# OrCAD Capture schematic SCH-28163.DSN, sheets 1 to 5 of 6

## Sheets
1 1. Title Page: title: FRDM-K64F; rev: D1; company: Freescale Semiconductor; note: SCH-28163 | PDF: SPF-28163; note: 6501 William Cannon Drive West; note: Austin, TX 78735-8598
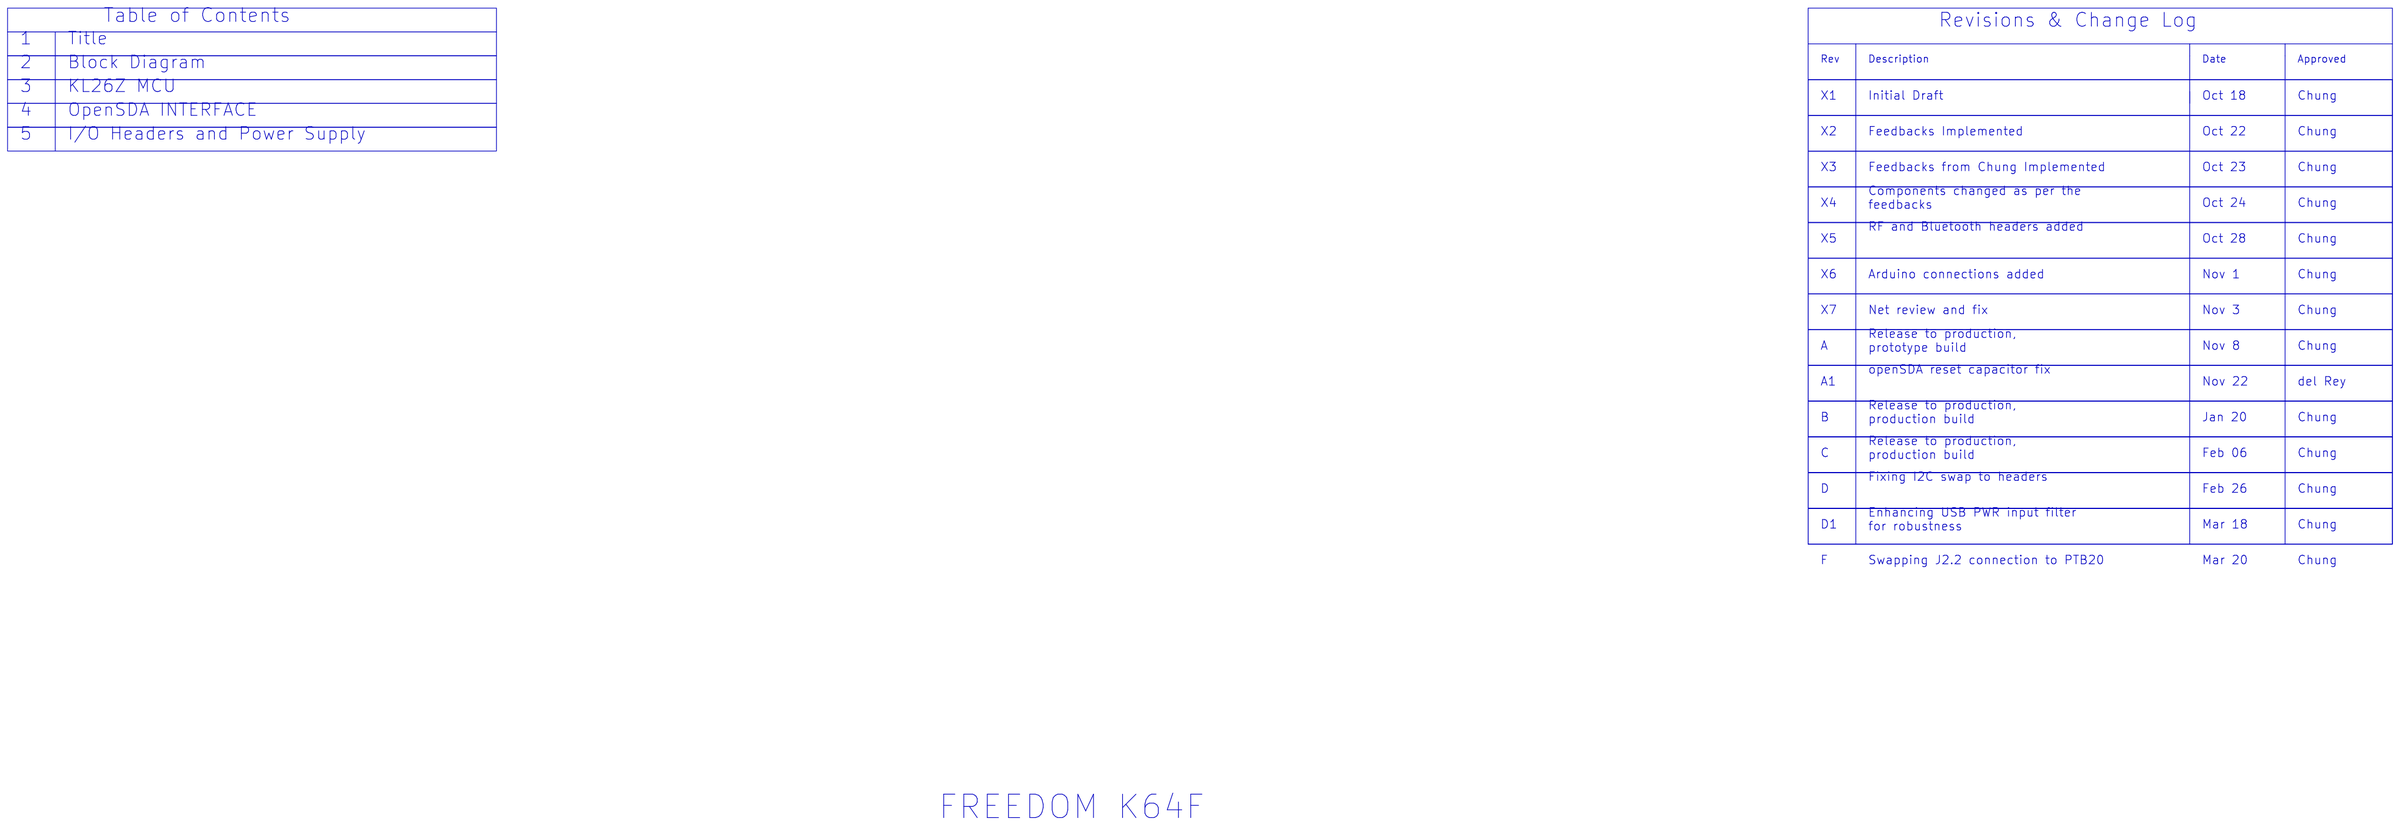
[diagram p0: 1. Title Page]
2 2. KL64F MCU: size C
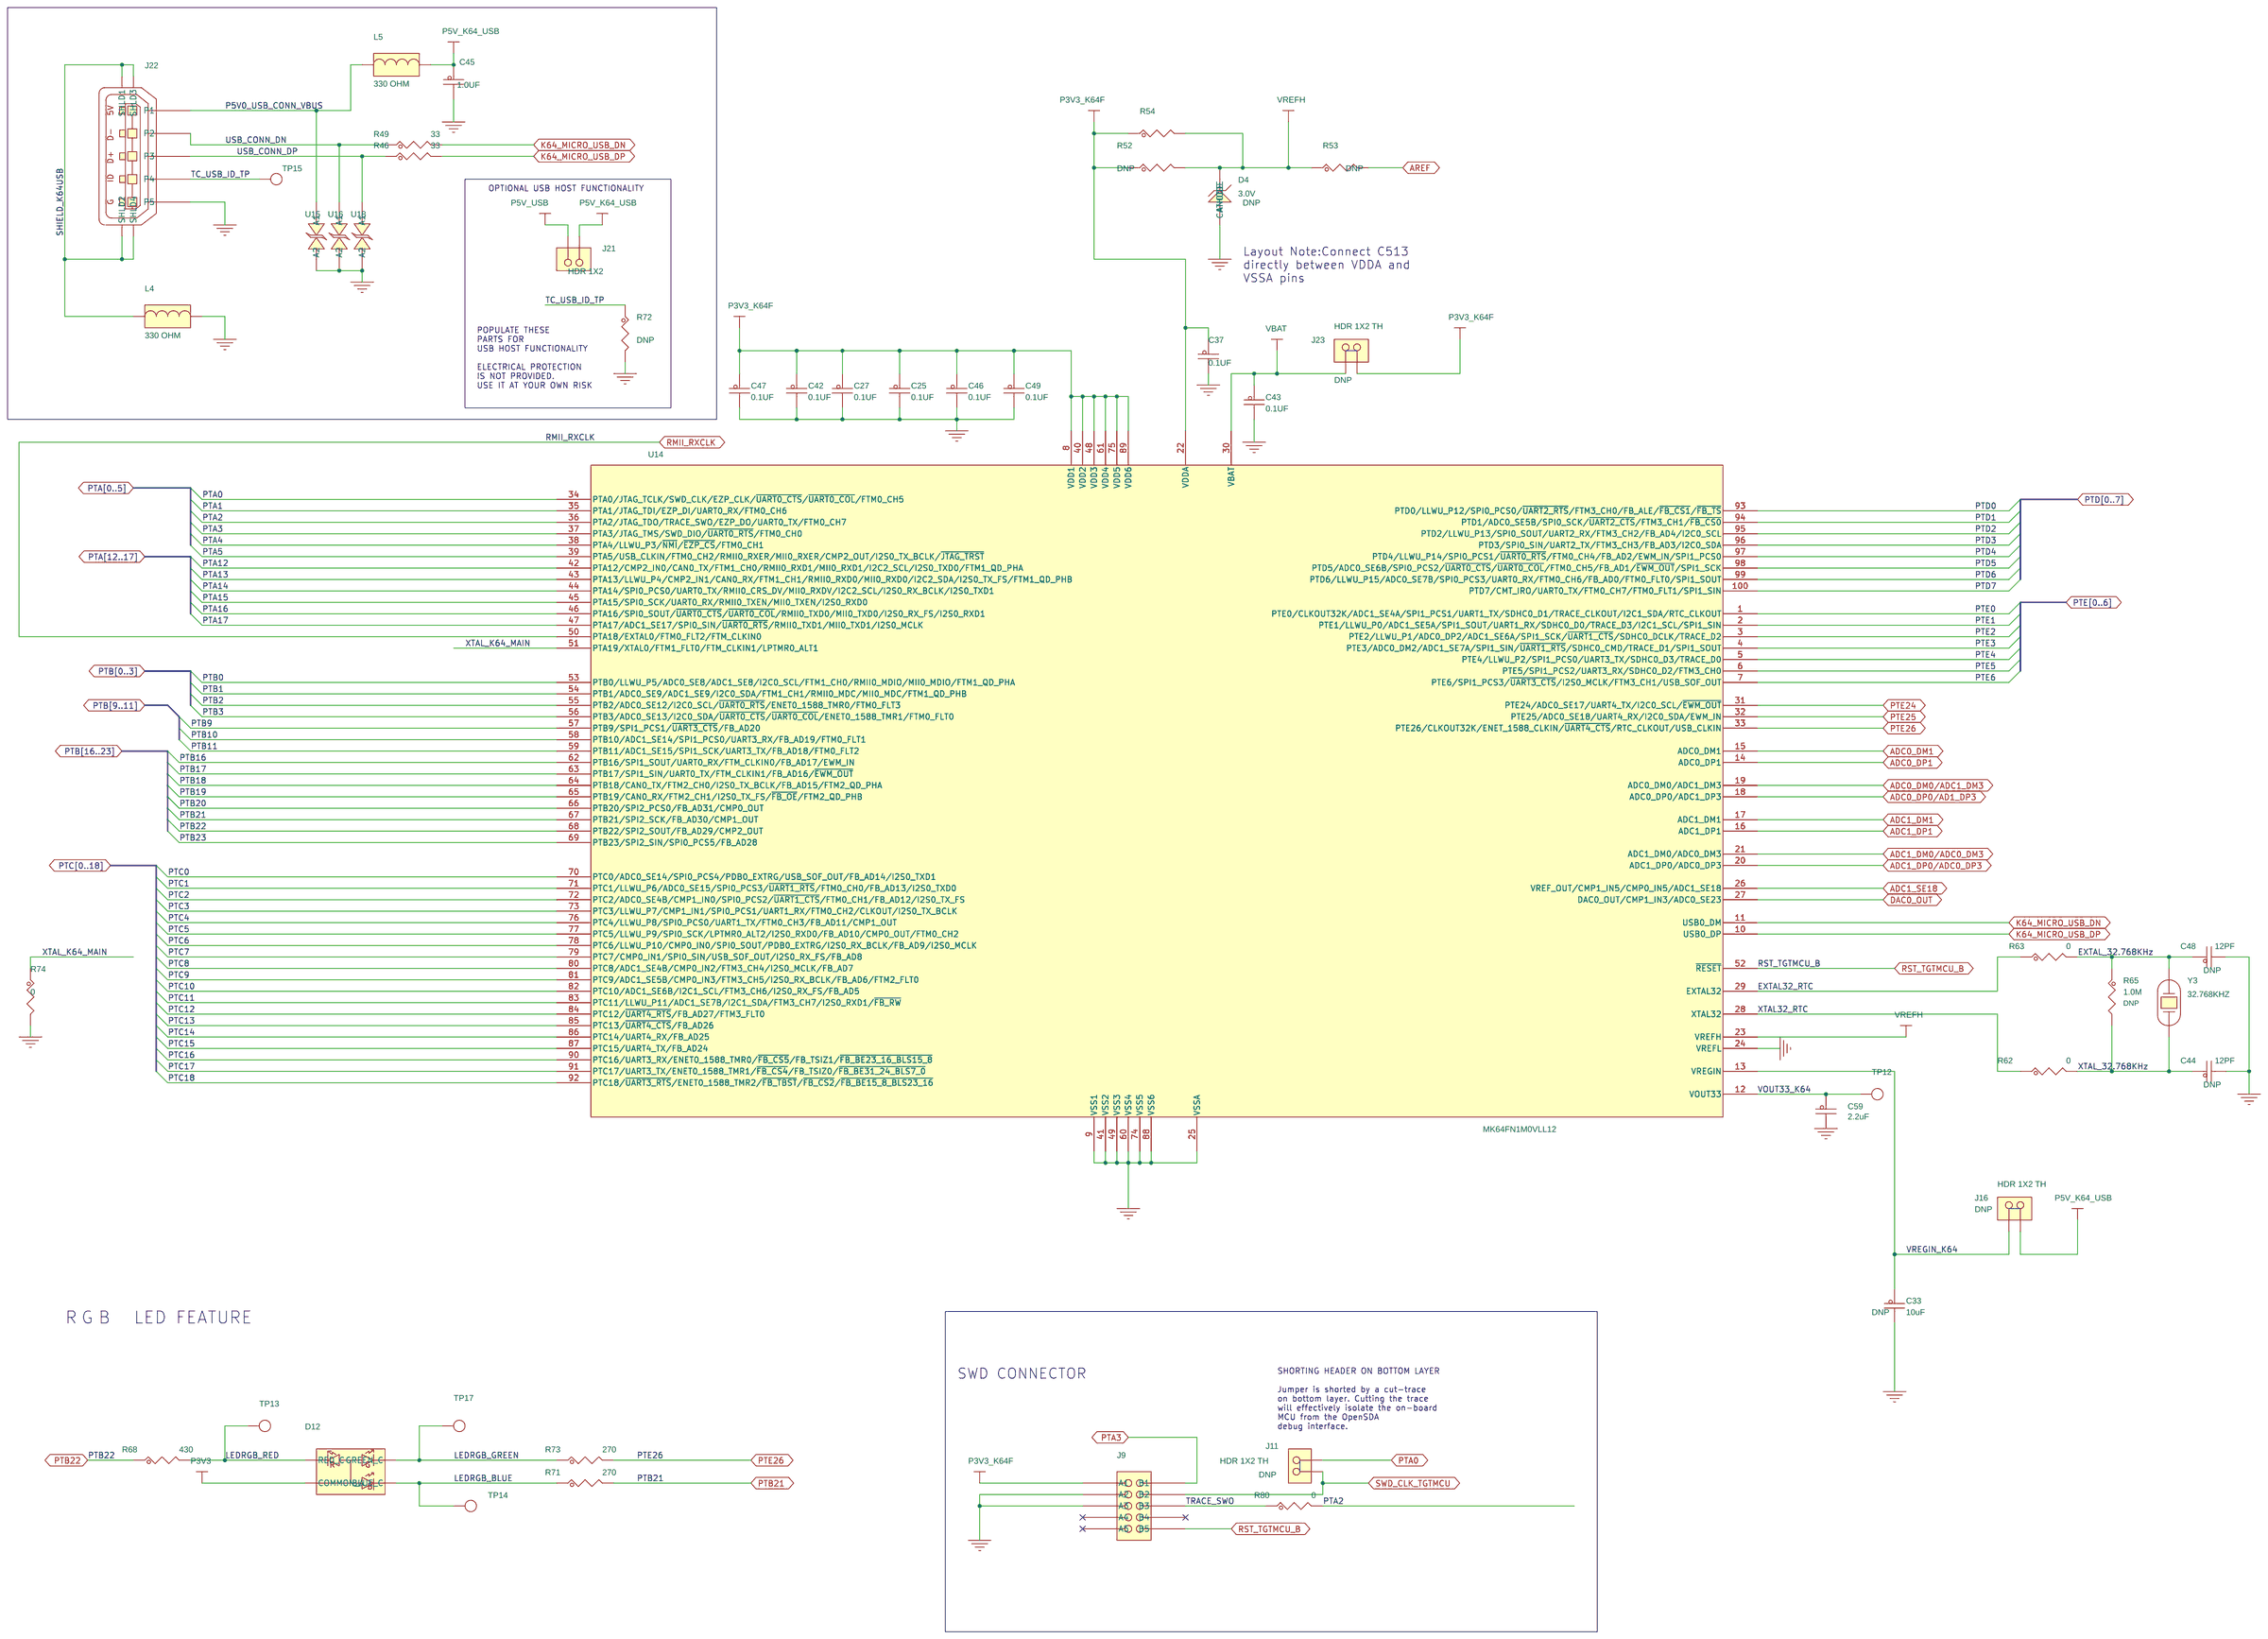
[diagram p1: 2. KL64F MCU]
3 3. OpenSDA interface: size D
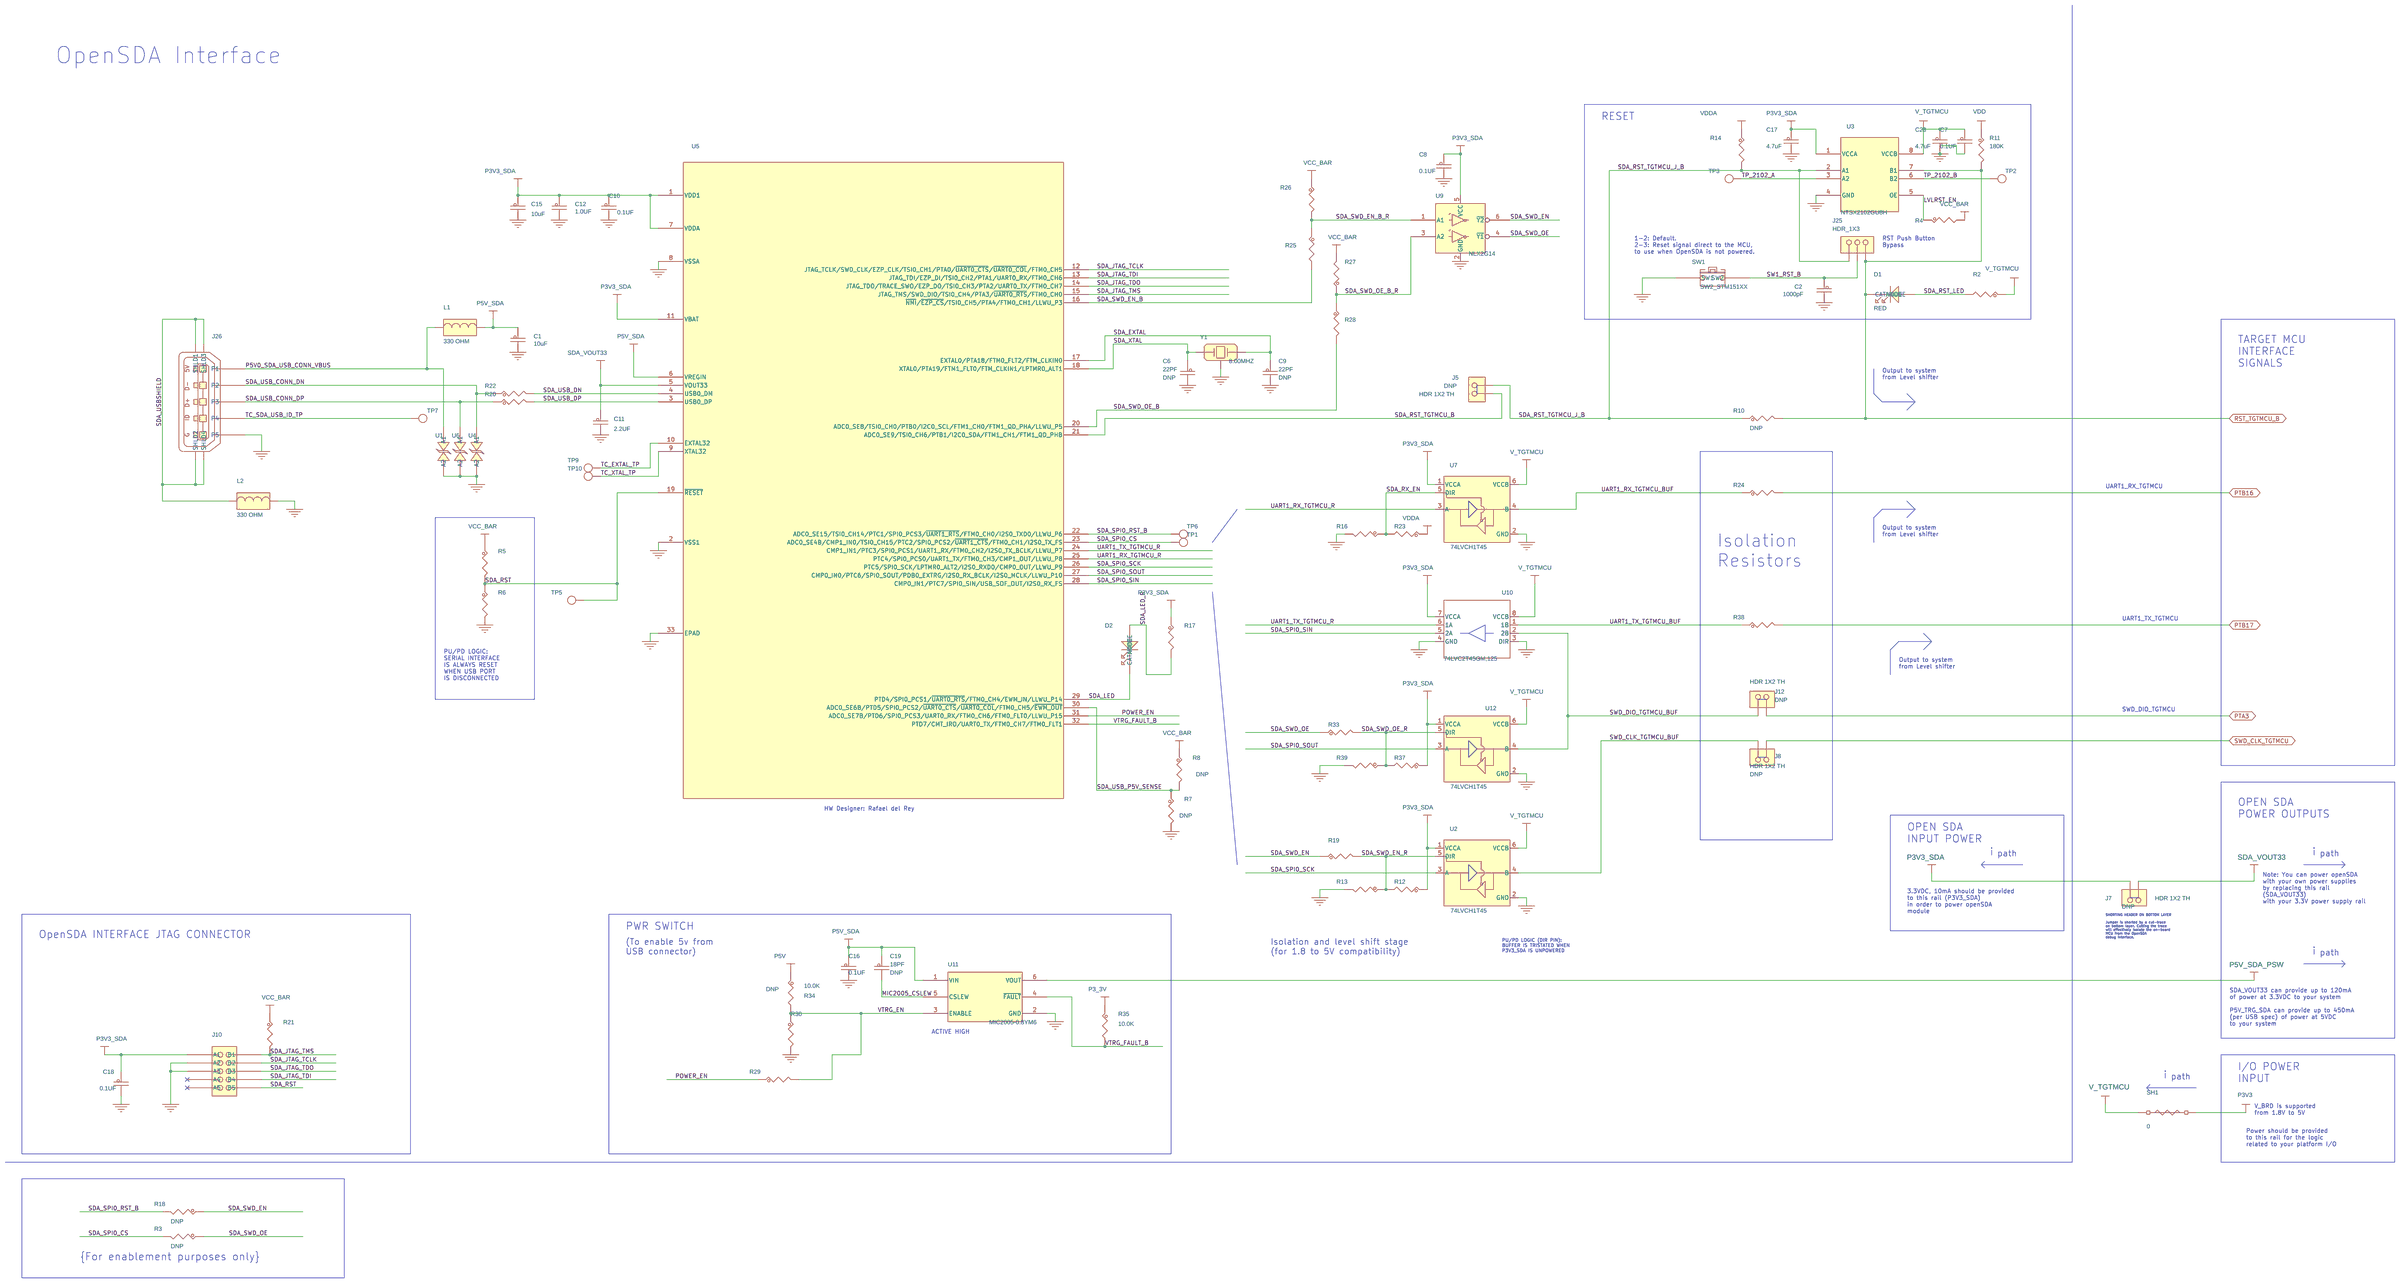
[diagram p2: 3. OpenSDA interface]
4 5. SD_Card: size C
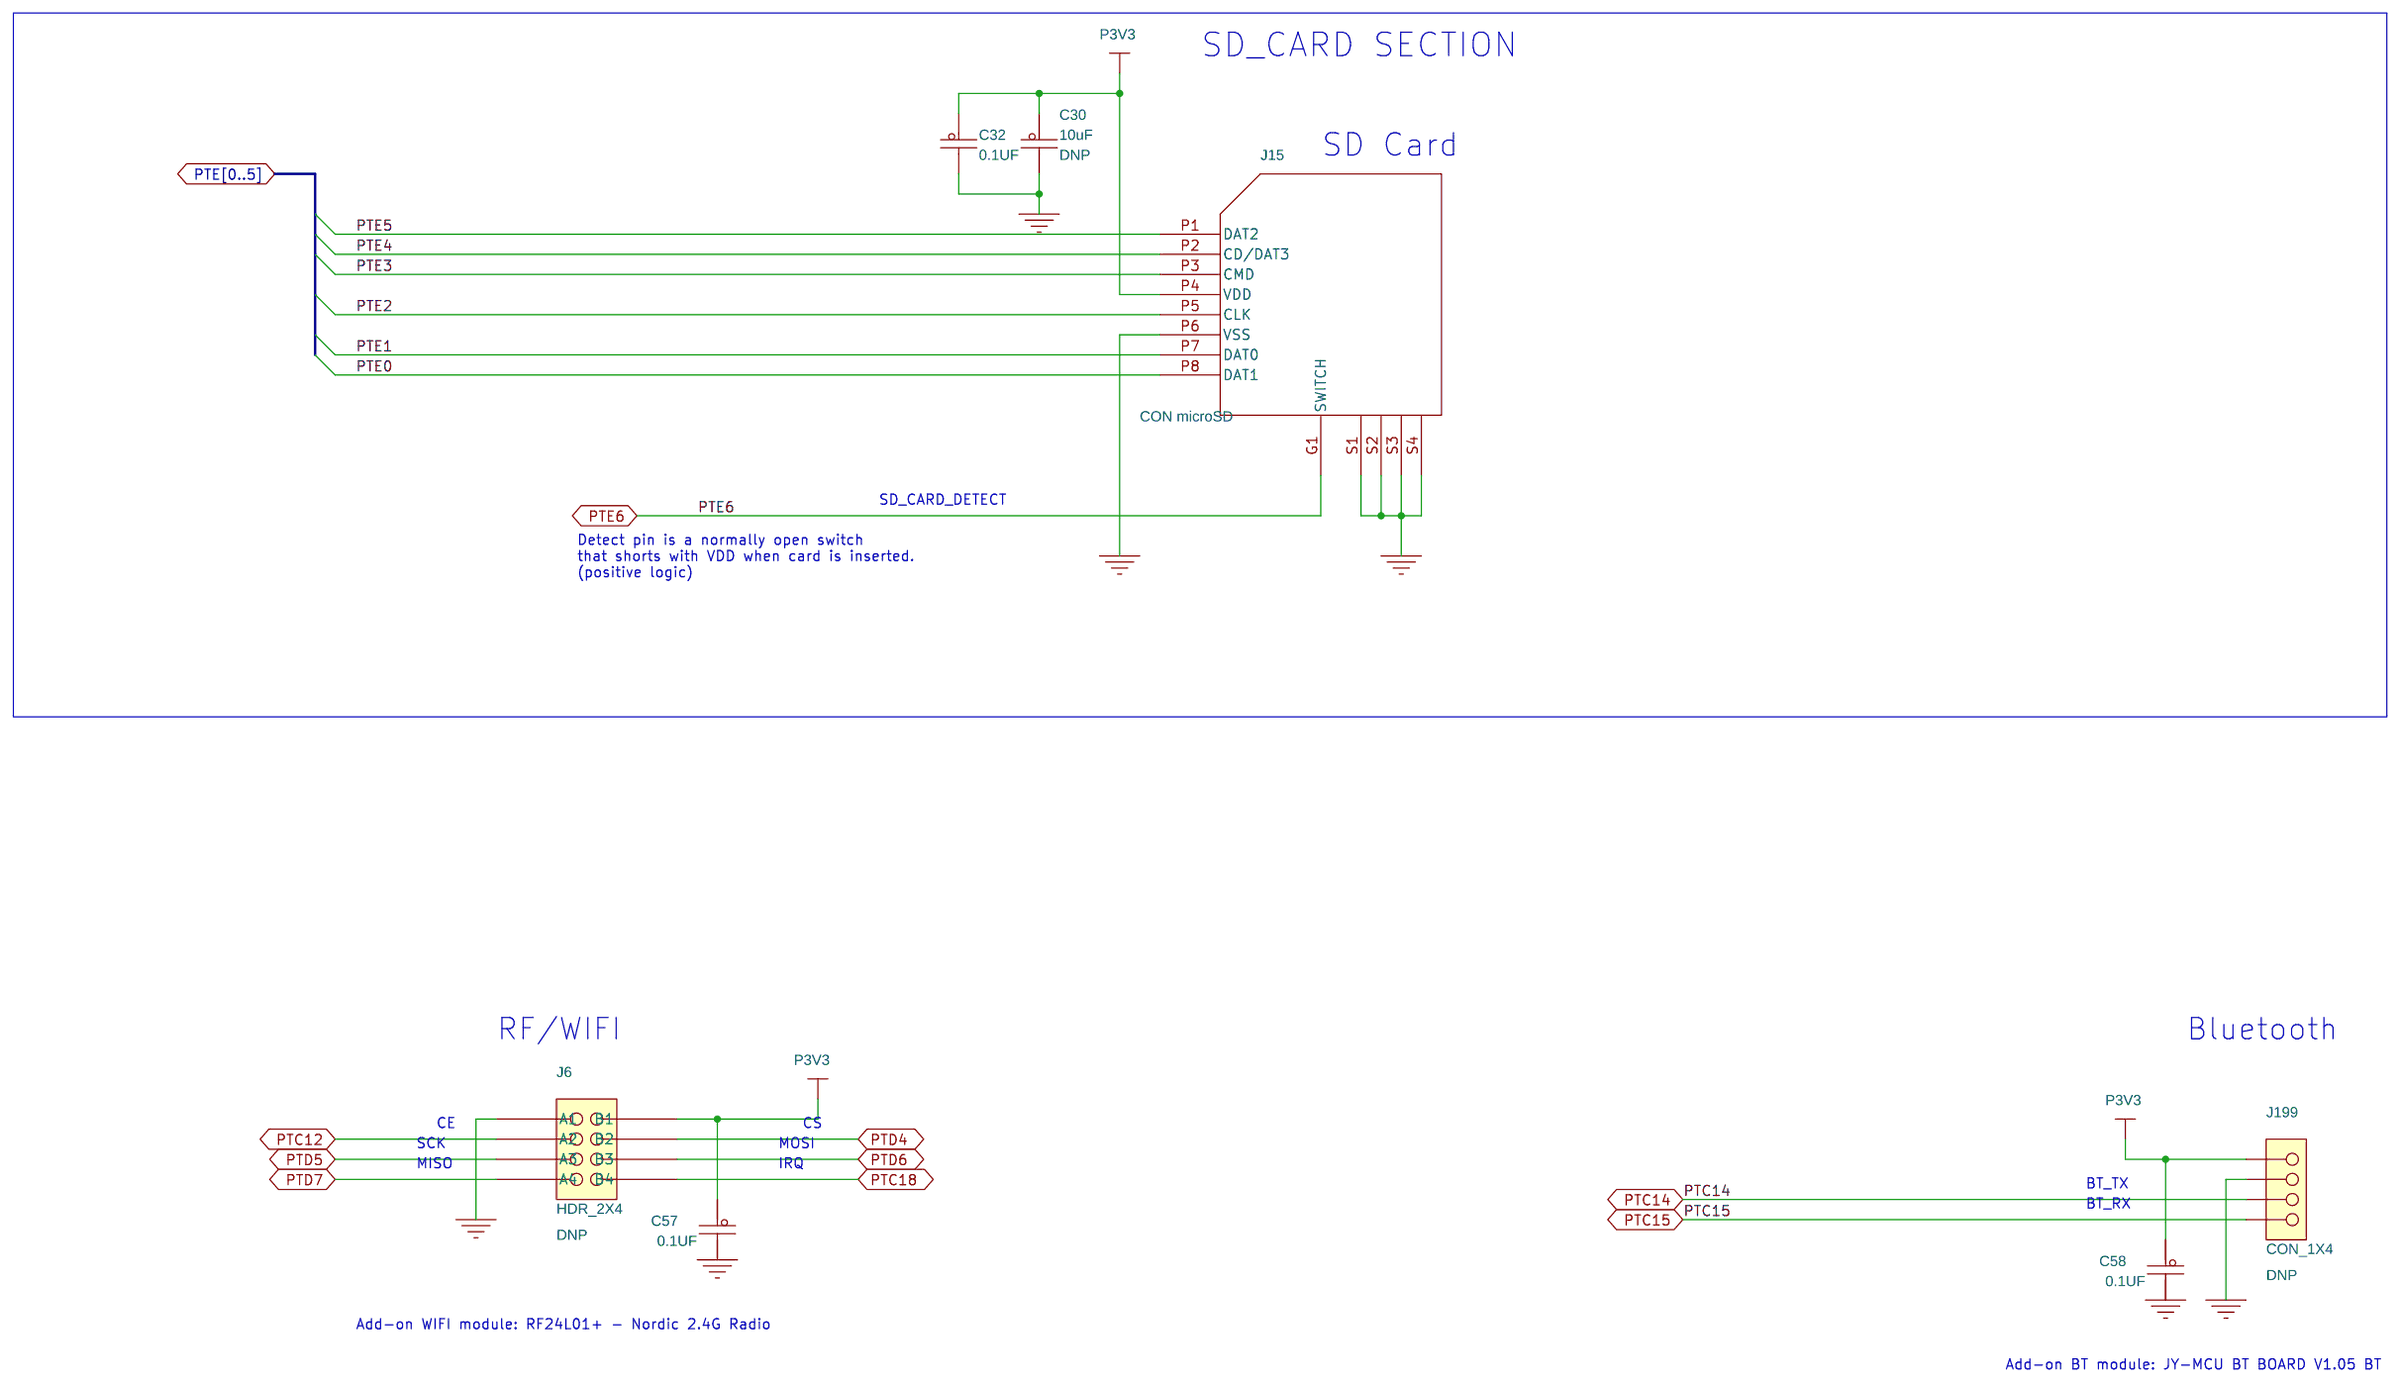
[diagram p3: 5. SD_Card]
5 6. RMII Section: size C
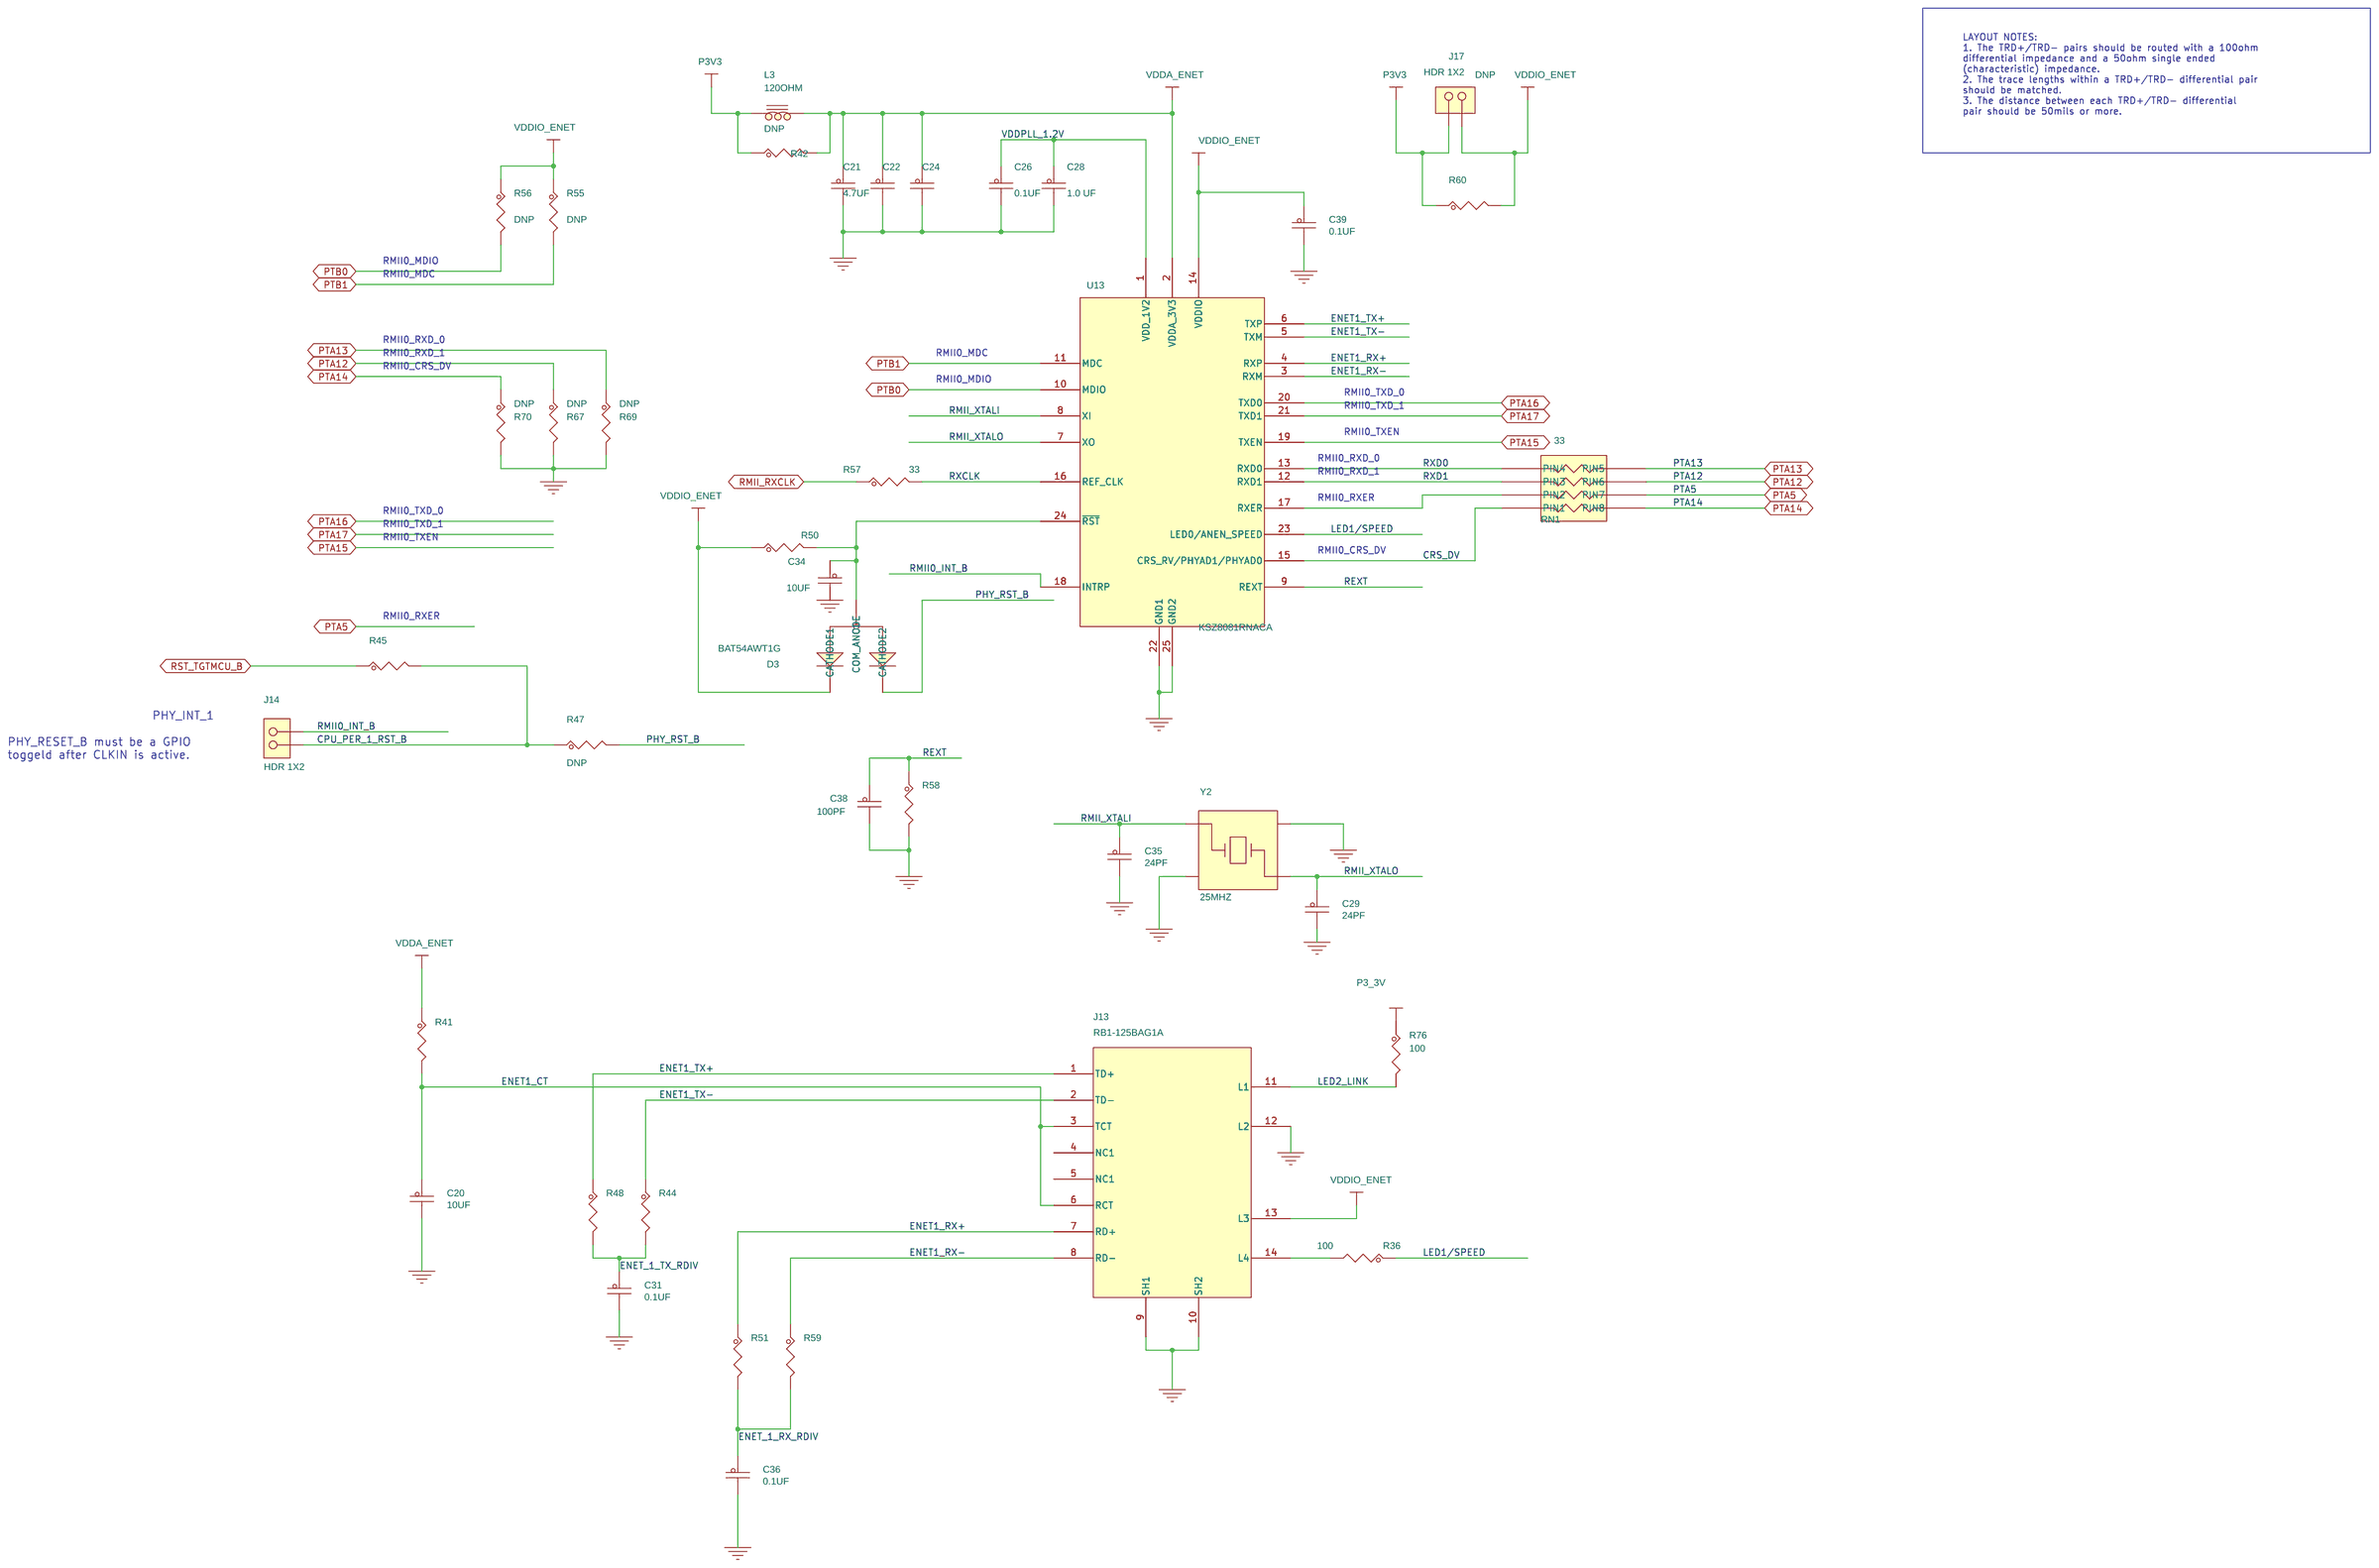
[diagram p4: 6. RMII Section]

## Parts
sheet 2. KL64F MCU
C25  0.1UF  [CC0402_25]
C27  0.1UF  [CC0402_25]
C33  10uF  [CC0603_OV]
C37  0.1UF  [CC0402_25]
C42  0.1UF  [CC0402_25]
C43  0.1UF  [CC0402_25]
C44  12PF  [CC0402_25]
C45  1.0UF  [CC0402_25]
C46  0.1UF  [CC0402_25]
C47  0.1UF  [CC0402_25]
C48  12PF  [CC0402_25]
C49  0.1UF  [CC0402_25]
C59  2.2uF  [CC0402_25]
D4  3.0V  [sod-323-A]
D12  CLV1A-FKB-CJ1M1F1BB7R4S3  [led4_3p4x3mm_smt]
J9  HDR 2X5  [hdr_5X2_ftsh_th_nsp]
J11  HDR 1X2 TH  [SH_HDR102_BOTTOM]
J16  HDR 1X2 TH  [SH_HDR102_BOTTOM]
J21  HDR 1X2  [hdr102]
J22  MICRO USB AB 5  [con5_microusb]
J23  HDR 1X2 TH  [SH_HDR102_BOTTOM]
L4  330 OHM  [ind_1608]
L5  330 OHM  [ind_1608]
R46  33  [RC0603_OV]
R49  33  [RC0603_OV]
R52  1K  [RC0603_OV]
R53  0  [RC0402_25]
R54  0  [RC0402_25]
R62  0  [RC0402_25]
R63  0  [RC0402_25]
R65  1.0M  [RC0603_OV]
R68  430  [RC0402_25]
R71  270  [RC0402_25]
R72  0  [RC0402_25]
R73  270  [RC0402_25]
R74  0  [RC0402_25]
R80  0  [RC0402_25]
TP12  TPAD_030  [TPAD_030]
TP13  TPAD_030  [TPAD_030]
TP14  TPAD_030  [TPAD_030]
TP15  TPAD_030  [TPAD_030]
TP17  TPAD_030  [TPAD_030]
U14  MK64FN1M0VLL12  [LQFP100_0P5_14X14]
U15  0402ESDA-MLP  [0402_mlp]
U16  0402ESDA-MLP  [0402_mlp]
U18  0402ESDA-MLP  [0402_mlp]
Y3  32.768KHZ  [XTAL2-3P2X1P5-SM]
sheet 3. OpenSDA interface
C1  10uF  [CC0402_25]
C2  1000pF  [CC0402_25]
C6  22PF  [CC0402_25]
C7  0.1UF  [CC0402_25]
C8  0.1UF  [CC0402_25]
C9  22PF  [CC0402_25]
C10  0.1UF  [CC0402_25]
C11  2.2UF  [CC0603_OV]
C12  1.0UF  [CC0402_25]
C15  10uF  [CC0603_OV]
C16  0.1UF  [CC0402_25]
C17  4.7uF  [CC0402_25]
C18  0.1UF  [CC0402_25]
C19  18PF  [CC0603_OV]
C23  4.7uF  [CC0402_25]
D1  RED  [LED_0603]
D2  LED GREEN  [LED_0603]
J5  HDR 1X2 TH  [SH_HDR102_BOTTOM]
J7  HDR 1X2 TH  [SH_HDR102_BOTTOM]
J8  HDR 1X2 TH  [SH_HDR102_BOTTOM]
J10  HDR 2X5  [hdr_5X2_ftsh_th_nsp]
J12  HDR 1X2 TH  [SH_HDR102_BOTTOM]
J25  HDR_1X3  [HDR103]
J26  MICRO USB AB 5  [con5_microusb]
L1  330 OHM  [ind_1608]
L2  330 OHM  [ind_1608]
R2  100  [RC0402_25]
R3  0  [RC0402_25]
R4  4.7K  [RC0402_25]
R5  4.7K  [RC0402_25]
R6  10.0K  [RC0402_25]
R7  10.0K  [RC0402_25]
R8  4.7K  [RC0402_25]
R10  0  [RC0402_25]
R11  180K  [RC0402_25]
R12  4.7K  [RC0402_25]
R13  10.0K  [RC0402_25]
R14  10.0K  [RC0402_25]
R16  10.0K  [RC0402_25]
R17  220  [RC0603_OV]
R18  0  [RC0402_25]
R19  0  [RC0402_25]
R20  33  [RC0402_25]
R21  10.0K  [RC0402_25]
R22  33  [RC0402_25]
R23  4.7K  [RC0402_25]
R24  0  [RC0402_25]
R25  0  [RC0402_25]
R26  10.0K  [RC0402_25]
R27  10.0K  [RC0402_25]
R28  0  [RC0402_25]
R29  1.0K  [RC0402_25]
R30  15K  [RC0402_25]
R33  0  [RC0402_25]
R34  10.0K  [RC0402_25]
R35  10.0K  [RC0402_25]
R37  4.7K  [RC0402_25]
R38  0  [RC0402_25]
R39  10.0K  [RC0402_25]
SH1  0  [SH0603]
SW1  SW2_STM151XX  [sw2_4x3mm_sm]
TP1  TPAD_030  [TPAD_030]
TP2  TPAD_030  [TPAD_030]
TP3  TPAD_030  [TPAD_030]
TP5  TPAD_030  [TPAD_030]
TP6  TPAD_030  [TPAD_030]
TP7  TPAD_030  [TPAD_030]
TP9  TPAD_030  [TPAD_030]
TP10  TPAD_030  [TPAD_030]
U1  0402ESDA-MLP  [0402_mlp]
U2  74LVCH1T45  [udfn6_1x1p5mm]
U3  NTSX2102GU8H  [xqfn8_1p45x1p25mm]
U4  0402ESDA-MLP  [0402_mlp]
U5  MK20DX128VFM5  [QFN32_S142EP]
U6  0402ESDA-MLP  [0402_mlp]
U7  74LVCH1T45  [udfn6_1x1p5mm]
U9  NLX2G14  [ullga6_1p45x1_0p5mm]
U10  74LVC2T45GM,125  [qfn8_1p6x1p6mm]
U11  MIC2005-0.8YM6  [SOT23-6_a]
U12  74LVCH1T45  [udfn6_1x1p5mm]
Y1  8.00MHZ  [xtal3_3p35x1p45_sm]
sheet 5. SD_Card
C30  10uF  [CC0603_OV]
C32  0.1UF  [CC0402_25]
C57  0.1UF  [CC0402_25]
C58  0.1UF  [CC0402_25]
J6  HDR_2X4  [HDR2X4]
J15  CON microSD  [con8_sdcard_push_sm]
J199  CON_1X4  [con1x4_100_th_ra]
sheet 6. RMII Section
C20  10UF  [CC0603_OV]
C21  4.7UF  [CC0603_OV]
C22  0.1UF  [CC0402_25]
C24  0.1UF  [CC0402_25]
C26  0.1UF  [CC0402_25]
C28  1.0 UF  [CC0603_OV]
C29  24PF  [CC0402_25]
C31  0.1UF  [CC0402_25]
C34  10UF  [CC0603_OV]
C35  24PF  [CC0402_25]
C36  0.1UF  [CC0402_25]
C38  100PF  [CC0603_OV]
C39  0.1UF  [CC0402_25]
D3  BAT54AWT1G  [sot323_3p]
J13  RB1-125BAG1A  [con_rj45_8p_2p54_th_ra]
J14  HDR 1X2  [hdr102]
J17  HDR 1X2  [hdr102]
L3  120OHM  [0603_CC]
R36  100  [RC0402_25]
R41  0  [RC0402_25]
R42  0  [RC0402_25]
R44  49.9  [RC0603_OV]
R45  0  [RC0402_25]
R47  0  [RC0402_25]
R48  49.9  [RC0603_OV]
R50  10.0K  [RC0402_25]
R51  49.9  [RC0603_OV]
R55  1.5K  [RC0402_25]
R56  1.5K  [RC0402_25]
R57  33  [RC0402_25]
R58  6.49K  [RC0603_OV]
R59  49.9  [RC0603_OV]
R60  0  [RC0402_25]
R67  10.0K  [RC0402_25]
R69  10.0K  [RC0402_25]
R70  10.0K  [RC0402_25]
R76  100  [RC0402_25]
RN1  33  [rnet_38v_0603]
U13  KSZ8081RNACA  [qfn24_4x4mm_slug]
Y2  25MHZ  [xtal4_3p4x2p7]

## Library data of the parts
C7 C8 C10 C16 C18 C25 C27 C37 C42 C46 C47 C49 = CAP_NP: CAP CER 0.1UF 10V 10% X5R 0402; AGILE_PN: 150-75634; CAD_APPROVED: Yes; FPLIST: CC0402_25,CC0402_HD,0402_CC; HEIGHT: 0.64MM; MFG_NAME01: KEMET; MFG_PN01: C0402C104K8PAC; PRIORITY_PN: 021-00169; ROHS: Yes; SIGNAL_MODEL: DEFAULT_CAPACITOR_100000pF_2_1; TOL: 10%; Tolerance: 10%; VOLTAGE: 10V
C33 = CAP_NP: CAP CER 10uF 16V 20% X5R 0603; AGILE_PN: 150-79092; ASSY_OPT: DNP; CAD_APPROVED: Yes; FPLIST: CC0603_OV,CC0603,0603_CC; HEIGHT: 1mm; MFG_NAME01: TAIYO YUDEN; MFG_PN01: EMK107BBJ106MA-T; ROHS: Yes; SIGNAL_MODEL: DEFAULT_CAPACITOR_1e+07pF_1_2; Tolerance: 20%; VOLTAGE: 16V
C43 = CAP_NP: CAP CER 0.1UF 10V 10% X5R 0402; AGILE_PN: 150-75634; CAD_APPROVED: Yes; FPLIST: CC0402_25,CC0402_HD,0402_CC; HEIGHT: 0.64MM; MFG_NAME01: KEMET; MFG_PN01: C0402C104K8PAC; PRIORITY_PN: 021-00169; ROHS: Yes; SIGNAL_MODEL: DEFAULT_CAPACITOR_100000pF_1_2; TOL: 10%; Tolerance: 10%; VOLTAGE: 10V
C44 C48 = CAP_NP: CAP CER 12PF 50V 5% C0G 0402; AGILE_PN: 150-75680; ASSY_OPT: DNP; CAD_APPROVED: Yes; FPLIST: CC0402_25,CC0402_HD,0402_CC; HEIGHT: 0.55MM; MFG_NAME01: MURATA; MFG_PN01: GRM1555C1H120JZ01D; ROHS: Yes; Tolerance: 5%; VOLTAGE: 50V
C12 C45 = CAP_NP: CAP CER 1.0UF 10V 10% X5R 0402; AGILE_PN: 150-75772; CAD_APPROVED: Yes; FPLIST: CC0402_25,CC0402_HD,0402_CC; HEIGHT: 0.6MM; MFG_NAME01: YAGEO AMERICA; MFG_PN01: CC0402KRX5R6BB105; PRIORITY_PN: 021-00242; ROHS: Yes; SIGNAL_MODEL: DEFAULT_CAPACITOR_1e+06pF_2_1; VOLTAGE: 10V
C59 = CAP_NP: CAP CER 2.2uF 10V 10% X5R 0402; AGILE_PN: 150-78974; CAD_APPROVED: Yes; FPLIST: CC0402_25,CC0402_HD,0402_CC; HEIGHT: 0.55 MM; MFG_NAME01: TDK; MFG_PN01: C1005X5R1A225K; ROHS: Yes; Tolerance: 10%; VOLTAGE: 10V
D4 = ZDIODE: DIODE ZNR -- 3V 200MW SOD323; AGILE_PN: 480-78396; ASSY_OPT: DNP; CAD_APPROVED: Yes; HEIGHT: 1.1MM; MFG_NAME01: ON SEMICONDUCTOR; MFG_PN01: MM3Z3V0T1G; ROHS: Yes
D12 = CLV1A_LED_4P: LED RED BL GRN SGL 50/25/25mA SMT; AGILE_PN: 370-76567; CAD_APPROVED: Yes; HEIGHT: 2.1MM; MFG_NAME01: CREE, INC; ROHS: Yes
J9 J10 = CONN_HDR_5X2: HDR 2X5 TH 50MIL CTR 167H AU 91L; AGILE_PN: 210-80192; CAD_APPROVED: Yes; FPLIST: hdr_5X2_ftsh_th,hdr_5X2_ftsh_th_nsp; HEIGHT: 4.25MM; MFG_NAME01: ANYTRONIC CORPORATION LIMITED; MFG_PN01: 0922S0205011N6T-2LF; ROHS: Yes
J5 J7 J8 J11 J12 J16 J23 = CONN_HDR_2X1: HDR 1X2 TH 100MIL SP 339H AU 98L; AGILE_PN: 210-75439; ASSY_OPT: DNP; CAD_APPROVED: YES; FPLIST: HDR102,SH_HDR102_BOTTOM; HEIGHT: 8.71 MM; MFG_NAME01: SAMTEC; MFG_PN01: TSW-102-07-G-S; PRIORITY_PN: 028-00556; ROHS: Yes
J14 J21 = CONN_HDR_2X1: HDR 1X2 TH 100MIL SP 330H SN 115L; AGILE_PN: 210-76752; CAD_APPROVED: Yes; HEIGHT: 8.58MM; MFG_NAME01: Samtec; MFG_PN01: TSW-102-23-T-S; ROHS: Yes
J22 J26 = USB_MINI_AB_RECEPTACLE: CON 1X5 USB_MICRO_AB_RECEPTACLE RA SMT 0.65MM SP 105H AU; AGILE_PN: 211-78722; CAD_APPROVED: Yes; HEIGHT: 2.65MM; MFG_NAME01: Molex; MFG_PN01: 47589-0001; ROHS: Yes
L1 L2 L4 L5 = BEAD: IND FER BEAD 330OHM@100MHZ 1.7A 0603; AGILE_PN: 180-78156; CAD_APPROVED: Yes; FPLIST: ind_1608,0603_CC; HEIGHT: 0.95MM; MFG_NAME01: TDK; MFG_PN01: MPZ1608S331A; PART_TYPE: FERRITE\BEAD; ROHS: Yes; Tolerance: 25%
R46 R49 = RES: RES MF 33 OHM 1/10W 5% 0603; AGILE_PN: 470-75848; CAD_APPROVED: Yes; FPLIST: RC0603_OV,RC0603,0603_CC; MFG_NAME01: VISHAY INTERTECHNOLOGY; MFG_PN01: CRCW060333R0JNEA; ROHS: Yes; SIGNAL_MODEL: DEFAULT_RESISTOR_33.000000OHM_2_1; Tolerance: 5%
R52 = RES: RES MF 1.0K 1/10W 5% 0603; AGILE_PN: 470-75412; ASSY_OPT: DNP; CAD_APPROVED: YES; FPLIST: RC0603_OV,RC0603,0603_CC; MFG_NAME01: VENKEL COMPANY; MFG_PN01: CR0603-10W-102JT; ROHS: Yes; SIGNAL_MODEL: DEFAULT_RESISTOR_1000.000000OHM_2_1; Tolerance: 5%
R47 R53 R72 = RES: RES MF ZERO OHM 1/16W 5% 0402; AGILE_PN: 470-75394; ASSY_OPT: DNP; CAD_APPROVED: Yes; FPLIST: RC0603_OV,RC0603,R603-X2,0603_CC; MFG_NAME01: ROHM; MFG_PN01: MCR01MZPJ000; PRIORITY_PN: 006-00559; ROHS: Yes; SIGNAL_MODEL: DEFAULT_RESISTOR_0.001OHM_2_1; Tolerance: 5%; VOLTAGE: 1/16W
R42 R45 R54 R60 = RES: RES MF ZERO OHM 1/16W 5% 0402; AGILE_PN: 470-75394; CAD_APPROVED: Yes; FPLIST: RC0603_OV,RC0603,R603-X2,0603_CC; MFG_NAME01: ROHM; MFG_PN01: MCR01MZPJ000; PRIORITY_PN: 006-00559; ROHS: Yes; SIGNAL_MODEL: DEFAULT_RESISTOR_0.001OHM_2_1; Tolerance: 5%; VOLTAGE: 1/16W
R19 R25 R28 R33 R62 R63 R80 = RES: RES MF ZERO OHM 1/16W 5% 0402; AGILE_PN: 470-75394; CAD_APPROVED: Yes; FPLIST: RC0402_25,RC0402_HD,RC0402_X2,0402_CC; MFG_NAME01: ROHM; MFG_PN01: MCR01MZPJ000; PRIORITY_PN: 006-00559; ROHS: Yes; SIGNAL_MODEL: DEFAULT_RESISTOR_0.001OHM_2_1; Tolerance: 5%; VOLTAGE: 1/16W
R65 = RES: RES MF 1.0M 1/10W 5% 0603; AGILE_PN: 470-75846; ASSY_OPT: DNP; CAD_APPROVED: Yes; FPLIST: RC0603_OV,RC0603,0603_CC; MFG_NAME01: BOURNS; MFG_PN01: CR0603-JW-105ELF; ROHS: Yes; SIGNAL_MODEL: DEFAULT_RESISTOR_1OHM_1_2; Tolerance: 5%; VOLTAGE: 50V
R68 = RES: RES MF 430 OHM 1/16W 1% 0402; AGILE_PN: 470-30801; CAD_APPROVED: Yes; FPLIST: RC0402_25,RC0402_HD,0402_CC; MFG_NAME01: KOA SPEER; MFG_PN01: RK73H1ETTP4300F; ROHS: Yes; Tolerance: 1%
R71 R73 = RES: RES MF 270 OHM 1/16W 5% 0402; AGILE_PN: 470-30332; CAD_APPROVED: Yes; FPLIST: RC0402_25,RC0402_HD,0402_CC; MFG_NAME01: VISHAY INTERTECHNOLOGY; MFG_PN01: CRCW0402270RJNED; ROHS: Yes; Tolerance: 5%
R74 = RES: RES MF ZERO OHM 1/16W 5% 0402; AGILE_PN: 470-75394; CAD_APPROVED: Yes; FPLIST: RC0603_OV,RC0603,R603-X2,0603_CC; HEIGHT: 0.6MM; MFG_NAME01: ROHM; MFG_PN01: MCR01MZPJ000; PRIORITY_PN: 006-00559; ROHS: Yes; SIGNAL_MODEL: DEFAULT_RESISTOR_0.001OHM_1_2; TOL: 1%; Tolerance: 5%; VOLTAGE: 1/16W
TP1-TP3 TP6 TP7 TP9 TP10 TP12 TP15 = TESTLOOP: TEST POINT PAD 30MIL DIA SMT, NO PART TO ORDER; AGILE_PN: 211-76642; CAD_APPROVED: Yes; HEIGHT: 0.1MM; MFG_NAME01: NOTACOMPONENT; MFG_PN01: NOTACOMPONENT; ROHS: Yes
TP5 TP13 TP14 TP17 = TestLoop: TEST POINT PAD 30MIL DIA SMT, NO PART TO ORDER; AGILE_PN: 211-76642; CAD_APPROVED: Yes; HEIGHT: 0.1MM; MFG_NAME01: NOTACOMPONENT; MFG_PN01: NOTACOMPONENT; ROHS: Yes
U14 = K64FN1M0VLL12_100P: IC MCU 1MB FLASH 120MHZ 1.71-3.6V LQFP100; AGILE_PN: 344-02013; CAD_APPROVED: Yes; HEIGHT: 1.7MM; MFG_NAME01: FREESCALE SEMICONDUCTOR; ROHS: Yes; VOLTAGE: 1.71-3.6V
U1 U4 U6 U15 U16 U18 = DIODE_TVS_BIDIR: DIODE TVS BIDIR -- 30V 0402; AGILE_PN: 480-76179; CAD_APPROVED: Yes; HEIGHT: 0.44MM; MFG_NAME01: COOPER BUSSMANN; MFG_PN01: 0402ESDA-MLP1; PRIORITY_PN: 048-0402ESDA; ROHS: Yes
Y3 = XTAL: XTAL 32.768KHZ 12.5PF 20PPM 3.2X1.5MM SMT; AGILE_PN: 230-77653; CAD_APPROVED: Yes; HEIGHT: 0.9MM; MFG_NAME01: Abracon Corporation; MFG_PN01: ABS07-32.768KHZ-T; ROHS: Yes
C1 = CAP_NP: CAP CER 10uF 10V 20% X5R 0402; AGILE_PN: TMP-WF-21855; CAD_APPROVED: Yes; FPLIST: C0402_25,CC0402_HD,0402_CC; HEIGHT: 0.7MM; MFG_NAME01: SAMSUNG; MFG_PN01: CL05A106MP5NUNC; PRE_APN: 150-79255; PRIORITY_PN: 021-00242; ROHS: Yes; SIGNAL_MODEL: DEFAULT_CAPACITOR_1e+06pF_2_1; Tolerance: 20%; VOLTAGE: 10V
C2 = CAP_NP: CAP CER 1000PF 50V 5% C0G 0402; AGILE_PN: 150-76334; CAD_APPROVED: Yes; FPLIST: CC0402_25,CC0402_HD,0402_CC; HEIGHT: 0.55MM; MFG_NAME01: MURATA; MFG_PN01: GRM1555C1H102JA01D; ROHS: Yes; Tolerance: 5%; VOLTAGE: 50V
C6 C9 = CAP_NP: CAP CER 22PF 50V 5% C0G 0402; AGILE_PN: 150-75266; ASSY_OPT: DNP; CAD_APPROVED: Yes; FPLIST: CC0402_25,CC0402_HD,0402_CC; HEIGHT: 0.635MM; MFG_NAME01: AVX; MFG_PN01: 04025A220JAT2A; PRIORITY_PN: 021-00234; ROHS: Yes; SIGNAL_MODEL: DEFAULT_CAPACITOR_22.000000pF_2_1; Tolerance: 5%; VOLTAGE: 50V
C11 = CAP_NP: CAP CER 2.2UF 10V 10% X7R 0603; AGILE_PN: 150-78564; CAD_APPROVED: Yes; FPLIST: CC0603_OV,CC0603,0603_CC; HEIGHT: 1.25MM; MFG_NAME01: TAIYO YUDEN; MFG_PN01: LMK107B7225KA-T; ROHS: Yes; SIGNAL_MODEL: DEFAULT_CAPACITOR_2.2e+06pF_2_1; Tolerance: 10%; VOLTAGE: 10V
C15 = CAP_NP: CAP CER 10uF 16V 20% X5R 0603; AGILE_PN: 150-79092; CAD_APPROVED: Yes; FPLIST: CC0603_OV,CC0603,0603_CC; HEIGHT: 1mm; MFG_NAME01: TAIYO YUDEN; MFG_PN01: EMK107BBJ106MA-T; ROHS: Yes; SIGNAL_MODEL: DEFAULT_CAPACITOR_1e+07pF_2_1; TOL: 10%; Tolerance: 20%; VOLTAGE: 16V
C17 C23 = CAP_NP: CAP CER 4.7UF 6.3V 20% X5R 0402; AGILE_PN: 150-78463; CAD_APPROVED: Yes; FPLIST: CC0402_25,CC0402_HD,0402_CC; HEIGHT: 0.65MM; MFG_NAME01: VENKEL COMPANY; MFG_PN01: C0402X5R6R3-475MNP; PRIORITY_PN: 021-00169; ROHS: Yes; SIGNAL_MODEL: DEFAULT_CAPACITOR_4.7e+06pF_2_1; TOL: 10%; Tolerance: 20%; VOLTAGE: 6.3V
C19 = CAP_NP: CAP CER 18PF 50V 5% C0G 0603; AGILE_PN: 150-75116; ASSY_OPT: DNP; CAD_APPROVED: Yes; FPLIST: CC0603_OV,CC0603,0603_CC; HEIGHT: 0.90MM; MFG_NAME01: YAGEO AMERICA; MFG_PN01: CC0603JRNPO9BN180; PRIORITY_PN: 021-00320; ROHS: Yes; SIGNAL_MODEL: DEFAULT_CAPACITOR_18.000000pF_2_1; TOL: 5%; Tolerance: 5%; VOLTAGE: 50V
D1 = LED: LED ULTRA BRIGHT RED SGL 30MA 0603; AGILE_PN: 370-75079; CAD_APPROVED: Yes; HEIGHT: 0.9MM; MFG_NAME01: LITE ON; MFG_PN01: LTST-C190KRKT; ROHS: Yes
D2 = LED: LED GRN SGL 20MA 0603; AGILE_PN: 370-76565; CAD_APPROVED: Yes; HEIGHT: 0.67MM; MFG_NAME01: osram; MFG_PN01: LG L29K-G2J1-24-Z; ROHS: Yes
J25 = CONN_HDR_3X1: HDR 1X3 TH 100MIL SP 330H AU 98L; AGILE_PN: 210-75442; CAD_APPROVED: Yes; HEIGHT: 8.38 MM; MFG_NAME01: SAMTEC; MFG_PN01: HTSW-103-07-S-S; PRIORITY_PN: 028-00700; ROHS: Yes
R2 = RES: RES MF 100 OHM 1/16W 5% 0402; AGILE_PN: 470-75591; CAD_APPROVED: Yes; FPLIST: RC0402_25,RC0402_HD,RC0402_X2,0402_CC; HEIGHT: 0.55 MM; MFG_NAME01: VENKEL COMPANY; MFG_PN01: CR040216W101JT; ROHS: Yes; SIGNAL_MODEL: DEFAULT_RESISTOR_100.000000OHM_2_1; TOL: 1%; Tolerance: 5%
R3 R18 = RES: RES MF ZERO OHM 1/16W 5% 0402; AGILE_PN: 470-75394; ASSY_OPT: DNP; CAD_APPROVED: Yes; FPLIST: RC0402_25,RC0402_HD,RC0402_X2,0402_CC; MFG_NAME01: ROHM; MFG_PN01: MCR01MZPJ000; PRIORITY_PN: 006-00559; ROHS: Yes; SIGNAL_MODEL: DEFAULT_RESISTOR_0.001OHM_2_1; Tolerance: 5%; VOLTAGE: 1/16W
R4 R5 R12 R23 R37 = RES: RES MF 4.7K 1/16W 5% 0402; AGILE_PN: 470-75626; CAD_APPROVED: Yes; FPLIST: RC0402_25,RC0402_HD,0402_CC; HEIGHT: 0.55 MM; MFG_NAME01: YAGEO AMERICA; MFG_PN01: RC0402JR-074K7L; ROHS: Yes; SIGNAL_MODEL: DEFAULT_RESISTOR_4700OHM_2_1; TOL: 1%; Tolerance: 5%
R6 R21 = RES: RES MF 10.0K 1/16W 1% AEC-Q200 0402; AGILE_PN: 470-75416; CAD_APPROVED: Yes; FPLIST: RC0402_25,RC0402_HD,0402_CC; MFG_NAME01: VISHAY INTERTECHNOLOGY; MFG_PN01: CRCW040210K0FKED; PRIORITY_PN: 006-00552; ROHS: Yes; SIGNAL_MODEL: DEFAULT_RESISTOR_10000OHM_2_1; Tolerance: 1%
R7 = RES: RES MF 10.0K 1/16W 1% AEC-Q200 0402; AGILE_PN: 470-75416; ASSY_OPT: DNP; CAD_APPROVED: Yes; FPLIST: RC0402_25,RC0402_HD,0402_CC; MFG_NAME01: VISHAY INTERTECHNOLOGY; MFG_PN01: CRCW040210K0FKED; PRIORITY_PN: 006-00552; ROHS: Yes; SIGNAL_MODEL: DEFAULT_RESISTOR_10000OHM_2_1; Tolerance: 1%
R8 = RES: RES MF 4.7K 1/16W 5% 0402; AGILE_PN: 470-75626; ASSY_OPT: DNP; CAD_APPROVED: Yes; FPLIST: RC0402_25,RC0402_HD,0402_CC; HEIGHT: 0.55 MM; MFG_NAME01: YAGEO AMERICA; MFG_PN01: RC0402JR-074K7L; ROHS: Yes; SIGNAL_MODEL: DEFAULT_RESISTOR_4700OHM_2_1; TOL: 1%; Tolerance: 5%
R10 = RES: RES MF ZERO OHM 1/16W 5% 0402; AGILE_PN: 470-75394; ASSY_OPT: DNP; CAD_APPROVED: Yes; FPLIST: RC0402_25,RC0402_HD,RC0402_X2,0402_CC; HEIGHT: 0.45 MM; MFG_NAME01: ROHM; MFG_PN01: MCR01MZPJ000; PRIORITY_PN: 006-00559; ROHS: Yes; SIGNAL_MODEL: DEFAULT_RESISTOR_0.001OHM_2_1; TOL: 5%; Tolerance: 5%; VOLTAGE: 1/16W
R11 = RES: RES MF 180K  1/16W 1% 0402; AGILE_PN: 470-31088; CAD_APPROVED: Yes; FPLIST: RC0402_25,RC0402_HD,0402_CC; MFG_NAME01: KOA SPEER; MFG_PN01: RK73H1ETTP1803F; ROHS: Yes; SIGNAL_MODEL: DEFAULT_RESISTOR_180000OHM_2_1; Tolerance: 1%
R13 R14 R16 R26 R27 R39 = RES: RES MF 10.0K 1/16W 1% AEC-Q200 0402; AGILE_PN: 470-75416; CAD_APPROVED: Yes; FPLIST: RC0402_25,RC0402_HD,0402_CC; HEIGHT: 0.55MM; MFG_NAME01: VISHAY INTERTECHNOLOGY; MFG_PN01: CRCW040210K0FKED; PRIORITY_PN: 006-00552; ROHS: Yes; SIGNAL_MODEL: DEFAULT_RESISTOR_10000OHM_2_1; TOL: 5%; Tolerance: 1%
R17 = RES: RES MF 220 OHM 1/10W 5% 0603; AGILE_PN: 470-30297; CAD_APPROVED: Yes; FPLIST: RC0603_OV,RC0603,0603_CC; MFG_NAME01: KOA SPEER; MFG_PN01: RK73B1JTTD221J; ROHS: Yes; SIGNAL_MODEL: DEFAULT_RESISTOR_220.000000OHM_2_1; Tolerance: 5%
R20 R22 R57 = RES: RES MF 33.0 OHM 1/16W 1% 0402; AGILE_PN: 470-75790; CAD_APPROVED: Yes; FPLIST: RC0402_25,RC0402_HD,RC0402_X2,0402_CC; MFG_NAME01: THYE MING TECH CO LTD; MFG_PN01: CR-02FL6---33R; PRIORITY_PN: 006-00556; ROHS: Yes; SIGNAL_MODEL: DEFAULT_RESISTOR_33.000000OHM_2_1; Tolerance: 1%
R24 R38 = RES: RES MF ZERO OHM 1/16W 5% 0402; AGILE_PN: 470-75394; CAD_APPROVED: Yes; FPLIST: RC0402_25,RC0402_HD,RC0402_X2,0402_CC; HEIGHT: 0.45 MM; MFG_NAME01: ROHM; MFG_PN01: MCR01MZPJ000; PRIORITY_PN: 006-00559; ROHS: Yes; SIGNAL_MODEL: DEFAULT_RESISTOR_0.001OHM_2_1; TOL: 5%; Tolerance: 5%; VOLTAGE: 1/16W
R29 = RES: RES MF 1.0K 1/16W 1% 0402; AGILE_PN: 470-76037; CAD_APPROVED: Yes; FPLIST: RC0402_25,RC0402_HD,RC0402_X2,0402_CC; HEIGHT: 0.4MM; MFG_NAME01: YAGEO AMERICA; MFG_PN01: RC0402FR-071KL; PRIORITY_PN: 006-00553; ROHS: Yes; SIGNAL_MODEL: DEFAULT_RESISTOR_1000.000000OHM_2_1; TOL: 1%; Tolerance: 1%; VOLTAGE: 1/16W
R30 = RES: RES MF 15K  1/16W 1% 0402; AGILE_PN: 470-30965; CAD_APPROVED: Yes; FPLIST: RC0402_25,RC0402_HD,0402_CC; HEIGHT: 0.4 MM; MFG_NAME01: KOA SPEER; MFG_PN01: RK73H1ETTP1502F; ROHS: Yes; SIGNAL_MODEL: DEFAULT_RESISTOR_15000OHM_2_1; TOL: 1%; Tolerance: 1%
R34 = RES: RES MF 10.0K 1/16W 1% AEC-Q200 0402; AGILE_PN: 470-75416; ASSY_OPT: DNP; CAD_APPROVED: Yes; FPLIST: RC0402_25,RC0402_HD,0402_CC; HEIGHT: 0.4MM; MFG_NAME01: VISHAY INTERTECHNOLOGY; MFG_PN01: CRCW040210K0FKED; PRIORITY_PN: 006-00552; ROHS: Yes; SIGNAL_MODEL: DEFAULT_RESISTOR_10000OHM_2_1; TOL: 1%; Tolerance: 1%
R35 = RES: RES MF 10.0K 1/16W 1% AEC-Q200 0402; AGILE_PN: 470-75416; CAD_APPROVED: Yes; FPLIST: RC0402_25,RC0402_HD,0402_CC; HEIGHT: 0.4MM; MFG_NAME01: VISHAY INTERTECHNOLOGY; MFG_PN01: CRCW040210K0FKED; PRIORITY_PN: 006-00552; ROHS: Yes; SIGNAL_MODEL: DEFAULT_RESISTOR_10000OHM_2_1; TOL: 1%; Tolerance: 1%
SH1 = RES_SHORT-2: ZERO OHM CUT TRACE 0603 PADS; NO PART TO ORDER; AGILE_PN: 470-80018; CAD_APPROVED: Yes; FPLIST: SH0603,SH0603_CC,SH0603-X2_PIN1TO2,SH0603-X2_PIN2TO3; MFG_NAME01: LAYOUT ELEMENT ONLY; MFG_PN01: LAYOUT ELEMENT ONLY; ROHS: Yes; SIGNAL_MODEL: DEFAULT_RESISTOR_0.001OHM_2_1
SW1 = SW2_STM151XX: SW SPST MOM NO TACT 12V 50MA SMT; AGILE_PN: 510-76958; CAD_APPROVED: Yes; HEIGHT: 2MM; MFG_NAME01: E SWITCH; MFG_PN01: TL1015BF160QG; ROHS: Yes
U2 U7 U12 = 74LVCH1T45_6P: IC XCVR 1BIT 3-STATE DUAL 1.2-5.5V XSON6; AGILE_PN: 312-80758; CAD_APPROVED: Yes; HEIGHT: 0.5MM; MFG_NAME01: NXP SEMICONDUCTORS; MFG_PN01: 74LVCH1T45GM,132; ROHS: Yes; VOLTAGE: 1.2-5.5V
U3 = NTSX2102GU8H_8P: IC DUAL SUPPLY XCVR 50 MBPS 5.5V XQFN8; AGILE_PN: 312-80763; CAD_APPROVED: Yes; HEIGHT: 0.5MM; MFG_NAME01: NXP Semiconductors; ROHS: Yes; VOLTAGE: 5.5V
U5 = PK20DX128V_QFN_32P: IC MCU FLASH 128KB 50MHZ 1.71-3.6V QFN32; AGILE_PN: 344-01231; CAD_APPROVED: Yes; HEIGHT: 1MM; MFG_NAME01: FREESCALE SEMICONDUCTOR; ROHS: Yes; VOLTAGE: 1.71-3.6V
U9 = NLU2GU04: IC INV DUAL SCHMITT TRIGGER 1.65-5.5V ULLGA6; AGILE_PN: 315-78830; CAD_APPROVED: Yes; HEIGHT: 0.4MM; MFG_NAME01: On Semiconductor; MFG_PN01: NLX2G14AMX1TCG; ROHS: Yes; VOLTAGE: 1.65-5.5V
U10 = 74LVC2T45GM_8P: IC XCVR DUAL SUPPLY 1.2 -5.5V XQFN8; AGILE_PN: 312-80762; CAD_APPROVED: Yes; HEIGHT: 0.5MM; MFG_NAME01: NXP Semiconductors; ROHS: Yes; VOLTAGE: 5.5V
U11 = MIC2005-0.8YM6: IC LIN SW PWR 0.8A 2.5-5.5V SOT23-6; AGILE_PN: 315-79199; CAD_APPROVED: Yes; HEIGHT: 1.45MM; MFG_NAME01: MICREL; PRIORITY_PN: 051-MIC2005-08; ROHS: Yes; VOLTAGE: 2.5-5.5V
Y1 = XTAL_CS: XTAL 8.00MHZ RSN CERAMIC -- SMT; AGILE_PN: 230-77664; CAD_APPROVED: Yes; HEIGHT: 0.8MM; MFG_NAME01: MURATA; MFG_PN01: CSTCE8M00G55-R0; PRIORITY_PN: 048-00290; ROHS: Yes
C30 = CAP_NP: CAP CER 10uF 16V 20% X5R 0603; AGILE_PN: 150-79092; ASSY_OPT: DNP; CAD_APPROVED: Yes; FPLIST: CC0603_OV,CC0603,0603_CC; HEIGHT: 1mm; MFG_NAME01: TAIYO YUDEN; MFG_PN01: EMK107BBJ106MA-T; ROHS: Yes; SIGNAL_MODEL: DEFAULT_CAPACITOR_1e+07pF_2_1; Tolerance: 20%; VOLTAGE: 16V
C32 C57 C58 = CAP_NP: CAP CER 0.1UF 10V 10% X5R 0402; AGILE_PN: 150-75634; CAD_APPROVED: Yes; FPLIST: CC0402_25,CC0402_HD,0402_CC; HEIGHT: 0.64MM; MFG_NAME01: KEMET; MFG_PN01: C0402C104K8PAC; PRIORITY_PN: 021-00169; ROHS: Yes; SIGNAL_MODEL: DEFAULT_CAPACITOR_100000pF_2_1; Tolerance: 10%; VOLTAGE: 10V
J6 = CONN_HDR_4X2: HDR 2X4 TH 100MIL CTR 343H SN 100L; AGILE_PN: 210-80410; ASSY_OPT: DNP; CAD_APPROVED: Yes; HEIGHT: 8.71 MM; MFG_NAME01: SAMTEC; MFG_PN01: TSW-104-07-T-D; ROHS: Yes
J15 = CON8_SDCARD_SW: CON 8 SD CARD PUSH SMT 1.1MM SP 75H AU; AGILE_PN: 211-79395; CAD_APPROVED: Yes; HEIGHT: 1.9 MM; MFG_NAME01: MOLEX; MFG_PN01: 1050270001; ROHS: Yes
J199 = CONN_HDR_4X1: CON 1X4 SKT RA SHRD TH 100MIL SP 108H AU 124L; AGILE_PN: 210-80454; ASSY_OPT: DNP; CAD_APPROVED: Yes; HEIGHT: 2.74MM; MFG_NAME01: SULLINS ELECTRONICS CORP; MFG_PN01: PPPC041LGBN-RC; ROHS: Yes
C20 C34 = CAP_NP: CAP CER 10UF 6.3V 10% X5R 0603; AGILE_PN: 150-77832; CAD_APPROVED: Yes; FPLIST: CC0603_OV,CC0603,0603_CC; HEIGHT: 1.0MM; MFG_NAME01: TDK; MFG_PN01: C1608X5R0J106KT; PRIORITY_PN: 021-00276; ROHS: Yes; SIGNAL_MODEL: DEFAULT_CAPACITOR_1e+07pF_2_1; Tolerance: 10%; VOLTAGE: 6.3V
C21 = CAP_NP: CAP CER 4.7UF 6.3V 10% X5R 0603; AGILE_PN: 150-75487; CAD_APPROVED: Yes; FPLIST: CC0603_OV,CC0603,CC0603_CC; HEIGHT: 1.016MM; MFG_NAME01: VENKEL COMPANY; MFG_PN01: C0603X5R6R3-475KNP; PRIORITY_PN: 021-00280; ROHS: Yes; ROOM: RMII_PHY; SIGNAL_MODEL: DEFAULT_CAPACITOR_4.7e+06pF_2_1; Tolerance: 10%; VOLTAGE: 6.3V
C22 C24 C26 = CAP_NP: CAP CER 0.1UF 16V 10% X7R 0402; AGILE_PN: 150-75182; CAD_APPROVED: Yes; FPLIST: CC0402_25,CC0402_HD,0402_CC; HEIGHT: 0.635MM; MFG_NAME01: KEMET; MFG_PN01: C0402C104K4RAC; PRIORITY_PN: 021-00196; ROHS: Yes; ROOM: RMII_PHY; SIGNAL_MODEL: DEFAULT_CAPACITOR_100000pF_2_1; TOL: 10%; Tolerance: 10%; VOLTAGE: 16V
C28 = CAP_NP: CAP CER 1.0UF 16V 10% X7R 0603; AGILE_PN: 150-30028; CAD_APPROVED: Yes; FPLIST: CC0603_OV,CC0603,0603_CC; HEIGHT: 1.0MM; MFG_NAME01: AVX; MFG_PN01: 0603YC105KAT2A; PRIORITY_PN: 021-00172; ROHS: Yes; ROOM: RMII_PHY; SIGNAL_MODEL: DEFAULT_CAPACITOR_1e+06pF_2_1; Tolerance: 10%; VOLTAGE: 16V
C29 C35 = CAP_NP: CAP CER 24PF 50V 5% C0G 0402; AGILE_PN: 150-77680; CAD_APPROVED: Yes; FPLIST: CC0402_25,CC0402_HD,0402_CC; HEIGHT: 0.55 MM; MFG_NAME01: MURATA; MFG_PN01: GRM1555C1H240JA01D; ROHS: Yes; SIGNAL_MODEL: DEFAULT_CAPACITOR_24.000000pF_2_1; Tolerance: 5%; VOLTAGE: 50V
C31 C36 C39 = CAP_NP: CAP CER 0.1UF 16V 10% X7R 0402; AGILE_PN: 150-75182; CAD_APPROVED: Yes; FPLIST: CC0402_25,CC0402_HD,0402_CC; HEIGHT: 0.635MM; MFG_NAME01: KEMET; MFG_PN01: C0402C104K4RAC; PRIORITY_PN: 021-00196; ROHS: Yes; ROOM: RMII_PHY; SIGNAL_MODEL: DEFAULT_CAPACITOR_100000pF_2_1; Tolerance: 10%; VOLTAGE: 16V
C38 = CAP_NP: CAP CER 100PF 50V 5% C0G 0603; AGILE_PN: 150-75286; CAD_APPROVED: Yes; FPLIST: CC0603_OV,CC0603,0603_CC; HEIGHT: 0.9mm; MFG_NAME01: AVX; MFG_PN01: 06035A101JAT2A; ROHS: Yes; SIGNAL_MODEL: DEFAULT_CAPACITOR_100.000000pF_2_1; Tolerance: 5%; VOLTAGE: 50V
D3 = DUALDIODE_CA_SOT23: DIODE SCH 200MA 30V SOT323; AGILE_PN: 480-78582; CAD_APPROVED: Yes; HEIGHT: 1MM; MFG_NAME01: ON SEMICONDUCTOR; ROHS: Yes
J13 = RJ45_RB1_125BAG1A: CON 8 RJ RA TH 2.54MM SP 580H AU 132L; AGILE_PN: 210-80460; CAD_APPROVED: Yes; HEIGHT: 14.6MM; MFG_NAME01: UDE CORP; ROHS: Yes
J17 = CONN_HDR_2X1: HDR 1X2 TH 100MIL SP 330H SN 115L; AGILE_PN: 210-76752; ASSY_OPT: DNP; CAD_APPROVED: Yes; HEIGHT: 8.58MM; MFG_NAME01: Samtec; MFG_PN01: TSW-102-23-T-S; ROHS: Yes
L3 = BEAD_0: IND FER BEAD 120OHM@100MHZ 2A 25% 0603; AGILE_PN: 180-30008; ASSY_OPT: DNP; CAD_APPROVED: Yes; FPLIST: IND_0603,0603_CC; HEIGHT: 0.95MM; MFG_NAME01: MURATA; MFG_PN01: BLM18PG121SH1; PART_TYPE: FERRITE; PRIORITY_PN: 024-00067; ROHS: Yes; ROOM: RMII_PHY; Tolerance: 25%
R36 R76 = RES: RES MF 100 OHM 1/32W 5% 0402; AGILE_PN: 470-30328; CAD_APPROVED: Yes; FPLIST: RC0402_25,RC0402_HD,0402_CC; MFG_NAME01: PANASONIC; MFG_PN01: ERAW33J101X; ROHS: Yes; Tolerance: 5%
R41 = RES: RES MF ZERO OHM 1/16W 5% 0402; AGILE_PN: 470-75394; CAD_APPROVED: Yes; FPLIST: RC0603_OV,RC0603,R603-X2,0603_CC; HEIGHT: 0.55MM; MFG_NAME01: ROHM; MFG_PN01: MCR01MZPJ000; PRIORITY_PN: 006-00559; ROHS: Yes; ROOM: RMII_PHY; SIGNAL_MODEL: DEFAULT_RESISTOR_0.001OHM_2_1; TOL: 5%; Tolerance: 5%; VOLTAGE: 1/16W
R44 R48 R51 R59 = RES: RES MF 49.9 OHM 1/10W 1% 0603; AGILE_PN: 470-75432; CAD_APPROVED: Yes; FPLIST: RC0603_OV,RC0603,0603_CC; HEIGHT: 0.55 MM; MFG_NAME01: KOA SPEER; MFG_PN01: RK73H1JTTD49R9F; PRIORITY_PN: 006-00482; ROHS: Yes; ROOM: RMII_PHY; SIGNAL_MODEL: DEFAULT_RESISTOR_49.900000OHM_2_1; TOL: 1%; Tolerance: 1%
R50 = RES: RES MF 10.0K 1/16W 1% AEC-Q200 0402; AGILE_PN: 470-75416; CAD_APPROVED: Yes; FPLIST: RC0402_25,RC0402_HD,0402_CC; MFG_NAME01: VISHAY INTERTECHNOLOGY; MFG_PN01: CRCW040210K0FKED; PRIORITY_PN: 006-00552; ROHS: Yes; ROOM: RMII_PHY; SIGNAL_MODEL: DEFAULT_RESISTOR_10000OHM_2_1; Tolerance: 1%
R55 R56 = RES: RES MF 1.50K 1/16W 1% 0402; AGILE_PN: 470-76065; ASSY_NOTE: 470-76065; ASSY_OPT: DNP; CAD_APPROVED: Yes; MFG_NAME01: VIKING TECH CORPORATION; MFG_PN01: CR-02FL6---1K5; PRIORITY_PN: 006-00654; ROHS: Yes; ROOM: RMII_PHY; SIGNAL_MODEL: DEFAULT_RESISTOR_1500OHM_2_1; TOLERANCE: 1%
R58 = RES: RES MF 6.49K 1/10W 1% 0603; AGILE_PN: 470-78028; CAD_APPROVED: Yes; FPLIST: RC0603_OV,RC0603,0603_CC; MFG_NAME01: KOA SPEER; MFG_PN01: RK73H1JTTD6491F; ROHS: Yes; SIGNAL_MODEL: DEFAULT_RESISTOR_6490OHM_2_1; Tolerance: 1%
R67 R69 R70 = RES: RES MF 10.0K 1/16W 1% AEC-Q200 0402; AGILE_PN: 470-75416; ASSY_OPT: DNP; CAD_APPROVED: Yes; FPLIST: RC0402_25,RC0402_HD,0402_CC; MFG_NAME01: VISHAY INTERTECHNOLOGY; MFG_PN01: CRCW040210K0FKED; PRIORITY_PN: 006-00552; ROHS: Yes; ROOM: RMII_PHY; SIGNAL_MODEL: DEFAULT_RESISTOR_10000OHM_2_1; Tolerance: 1%
RN1 = Resistor_Array: RNET ISO 4 33 OHM 1/16W 5% 0603; AGILE_PN: 470-80689; CAD_APPROVED: Yes; MFG_NAME01: PANASONIC; MFG_PN01: EXB-38V330JV; ROHS: Yes; Tolerance: 5%
U13 = KSZ8081RNACA_QFN_24P: IC XCVR 10/100M EPHY 3.3V QFN24; AGILE_PN: 312-80840; CAD_APPROVED: Yes; HEIGHT: 0.9MM; MFG_NAME01: MICREL; ROHS: Yes; VOLTAGE: 3.3V
Y2 = CRYSTAL13: XTAL 25MHZ 18PF -- SMT; AGILE_PN: 230-77979; CAD_APPROVED: Yes; HEIGHT: 0.8MM; MFG_NAME01: CTS; MFG_PN01: 403I35D25M00000; ROHS: Yes

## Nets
GND: C1.2 C2.2 C6.2 C7.2 C8.2 C9.2 C10.2 C11.2 C12.2 C15.2 C16.2 C17.2 C18.2 C20.2 C21.2 C22.2 C23.2 C24.2 C25.2 C26.2 C27.2 C28.2 C29.2 C30.2 C31.2 C32.2 C33.2 C34.2 C35.2 C36.2 C37.2 C38.2 C39.2 C42.2 C43.2 C44.2 C45.2 C46.2 C47.2 C48.2 C49.2 C57.2 C58.2 C59.2 D4.A(ANODE) J6.1(A1) J9.3(A2) J9.5(A3) J10.3(A2) J10.5(A3) J13.9(SH1) J13.10(SH2) J13.12(L2) J15.P6(VSS) J15.S1 J15.S2 J15.S3 J15.S4 J22.5(P5) J26.5(P5) J199.2 L2.2 L4.2 R6.2 R7.2 R13.2 R16.2 R30.2 R39.2 R58.2 R67.2 R69.2 R70.2 R72.2 R74.2 SW1.1(SW1) U1.2(A2) U2.2(GND) U3.4(GND) U4.2(A2) U5.2(VSS1) U5.8(VSSA) U5.33(EPAD) U6.2(A2) U7.2(GND) U9.2(GND) U10.3(DIR) U10.4(GND) U11.2(GND) U12.2(GND) U13.22(GND1) U13.25(GND2) U14.9(VSS1) U14.24(VREFL) U14.25(VSSA) U14.41(VSS2) U14.49(VSS3) U14.60(VSS4) U14.74(VSS5) U14.88(VSS6) U15.2(A2) U16.2(A2) U18.2(A2) Y1.2 Y2.2 Y2.4 ; also on sheet 6
P3V3: C30.1 C32.1 C57.1 C58.1 D12.2(COMMON_A) J6.2(B1) J15.P4(VDD) J17.2 J199.1 L3.1 R42.1 R60.1 SH1.2 ; also on sheet 6
P3V3_K64F: C25.1 C27.1 C37.1 C42.1 C46.1 C47.1 C49.1 J9.1(A1) J23.2 R52.1 R54.1 U14.8(VDD1) U14.22(VDDA) U14.40(VDD2) U14.48(VDD3) U14.61(VDD4) U14.75(VDD5) U14.89(VDD6) ; also on sheet 6
P3V3_SDA: C8.1 C10.1 C12.1 C15.1 C17.1 C18.1 J7.1 J10.1(A1) R4.2 R12.1 R14.1 R17.1 R21.1 R23.1 R26.1 R27.2 R35.1 R37.1 U2.1(VCCA) U3.1(VCCA) U5.1(VDD1) U5.7(VDDA) U5.11(VBAT) U7.1(VCCA) U9.5(VCC) U10.7(VCCA) U12.1(VCCA) ; also on sheet 6
P5V0_SDA_USB_CONN_VBUS: J26.1(P1) L1.1 U1.1(A1)
P5V0_USB_CONN_VBUS: J22.1(P1) L5.1 U15.1(A1)
P5V_K64_USB: C45.1 J16.2 J21.2 L5.2 ; also on sheet 6
P5V_SDA: C1.1 C16.1 C19.1 L1.2 R5.1 R8.1 R34.1 U5.6(VREGIN) U11.1(VIN)
P5V_SDA_PSW: U11.6(VOUT) ; also on sheet 6
P5V_USB: J21.1 ; also on sheet 6
VBAT: C43.1 J23.1 U14.30(VBAT)
VDDA_ENET: C21.1 C22.1 C24.1 L3.2 R41.1 R42.2 U13.2(VDDA_3V3)
VDDIO_ENET: C39.1 D3.1(CATHODE1) J13.13(L3) J17.1 R50.1 R55.1 R56.1 R60.2 R76.1 U13.14(VDDIO)
VDDPLL_1.2V: C26.1 C28.1 U13.1(VDD_1V2)
ADC0_DM0/ADC1_DM3: U14.19(ADC0_DM0/ADC1_DM3) ; also on sheet 6
ADC0_DM1: U14.15(ADC0_DM1) ; also on sheet 6
ADC0_DP0/AD1_DP3: U14.18(ADC0_DP0/ADC1_DP3) ; also on sheet 6
ADC0_DP1: U14.14(ADC0_DP1) ; also on sheet 6
ADC1_DM0/ADC0_DM3: U14.21(ADC1_DM0/ADC0_DM3) ; also on sheet 6
ADC1_DM1: U14.17(ADC1_DM1) ; also on sheet 6
ADC1_DP0/ADC0_DP3: U14.20(ADC1_DP0/ADC0_DP3) ; also on sheet 6
ADC1_DP1: U14.16(ADC1_DP1) ; also on sheet 6
ADC1_SE18: U14.26(VREF_OUT/CMP1_IN5/CMP0_IN5/ADC1_SE18) ; also on sheet 6
AREF: R53.2 ; also on sheet 6
CPU_PER_1_RST_B: J14.1 R45.2 R47.1
CRS_DV: RN1.1(PIN1) U13.15(CRS_RV/PHYAD1/PHYAD0)
DAC0_OUT: U14.27(DAC0_OUT/CMP1_IN3/ADC0_SE23) ; also on sheet 6
ENET1_CT: C20.1 J13.3(TCT) J13.6(RCT) R41.2
ENET1_RX+: J13.7(RD+) R51.1 U13.4(RXP)
ENET1_RX-: J13.8(RD-) R59.1 U13.3(RXM)
ENET1_TX+: J13.1(TD+) R48.1 U13.6(TXP)
ENET1_TX-: J13.2(TD-) R44.1 U13.5(TXM)
ENET_1_RX_RDIV: C36.1 R51.2 R59.2
ENET_1_TX_RDIV: C31.1 R44.2 R48.2
EXTAL32_RTC: R63.1 U14.29(EXTAL32)
EXTAL_32.768KHz: C48.1 R63.2 R65.1 Y3.2
K64_MICRO_USB_DN: R49.2 U14.11(USB0_DM)
K64_MICRO_USB_DP: R46.2 U14.10(USB0_DP)
LED1/SPEED: R36.1 U13.23(LED0/ANEN_SPEED)
LED2_LINK: J13.11(L1) R76.2
LEDRGB_BLUE: D12.3(BLUE_C) R71.1 TP14.1(Pin1)
LEDRGB_GREEN: D12.4(GREEN_C) R73.1 TP17.1(Pin1)
LEDRGB_RED: D12.1(RED_C) R68.2 TP13.1(Pin1)
LVLRST_EN: R4.1 U3.5(OE)
MIC2005_CSLEW: C19.2 U11.5(CSLEW)
NC1: J13.4(NC1) J13.5(NC1)
PHY_RST_B: D3.2(CATHODE2) R47.2
POWER_EN: R29.1 U5.31(ADC0_SE7B/PTD6/SPI0_PCS3/UART0_RX/FTM0_CH6/FTM0_FLT0/LLWU_P15)
PTA0: J11.1 U14.34(PTA0/JTAG_TCLK/SWD_CLK/EZP_CLK/~{UART0_CTS}/~{UART0_COL}/FTM0_CH5) ; also on sheet 6
PTA1: U14.35(PTA1/JTAG_TDI/EZP_DI/UART0_RX/FTM0_CH6) ; also on sheet 6
PTA2: R80.2 U14.36(PTA2/JTAG_TDO/TRACE_SWO/EZP_DO/UART0_TX/FTM0_CH7) ; also on sheet 6
PTA3: J9.2(B1) J12.2 U14.37(PTA3/JTAG_TMS/SWD_DIO/~{UART0_RTS}/FTM0_CH0)
PTA4: U14.38(PTA4/LLWU_P3/~{NMI}/~{EZP_CS}/FTM0_CH1) ; also on sheet 6
PTA5: RN1.7(PIN7) U14.39(PTA5/USB_CLKIN/FTM0_CH2/RMII0_RXER/MII0_RXER/CMP2_OUT/I2S0_TX_BCLK/~{JTAG_TRST})
PTA12: R67.1 RN1.6(PIN6) U14.42(PTA12/CMP2_IN0/CAN0_TX/FTM1_CH0/RMII0_RXD1/MII0_RXD1/I2C2_SCL/I2S0_TXD0/FTM1_QD_PHA)
PTA13: R69.1 RN1.5(PIN5) U14.43(PTA13/LLWU_P4/CMP2_IN1/CAN0_RX/FTM1_CH1/RMII0_RXD0/MII0_RXD0/I2C2_SDA/I2S0_TX_FS/FTM1_QD_PHB)
PTA14: R70.1 RN1.8(PIN8) U14.44(PTA14/SPI0_PCS0/UART0_TX/RMII0_CRS_DV/MII0_RXDV/I2C2_SCL/I2S0_RX_BCLK/I2S0_TXD1)
PTA15: U13.19(TXEN) U14.45(PTA15/SPI0_SCK/UART0_RX/RMII0_TXEN/MII0_TXEN/I2S0_RXD0)
PTA16: U13.20(TXD0) U14.46(PTA16/SPI0_SOUT/~{UART0_CTS}/~{UART0_COL}/RMII0_TXD0/MII0_TXD0/I2S0_RX_FS/I2S0_RXD1)
PTA17: U13.21(TXD1) U14.47(PTA17/ADC1_SE17/SPI0_SIN/~{UART0_RTS}/RMII0_TXD1/MII0_TXD1/I2S0_MCLK)
PTB0: R56.2 U13.10(MDIO) U14.53(PTB0/LLWU_P5/ADC0_SE8/ADC1_SE8/I2C0_SCL/FTM1_CH0/RMII0_MDIO/MII0_MDIO/FTM1_QD_PHA)
PTB1: R55.2 U13.11(MDC) U14.54(PTB1/ADC0_SE9/ADC1_SE9/I2C0_SDA/FTM1_CH1/RMII0_MDC/MII0_MDC/FTM1_QD_PHB)
PTB2: U14.55(PTB2/ADC0_SE12/I2C0_SCL/~{UART0_RTS}/ENET0_1588_TMR0/FTM0_FLT3) ; also on sheet 6
PTB3: U14.56(PTB3/ADC0_SE13/I2C0_SDA/~{UART0_CTS}/~{UART0_COL}/ENET0_1588_TMR1/FTM0_FLT0) ; also on sheet 6
PTB9: U14.57(PTB9/SPI1_PCS1/~{UART3_CTS}/FB_AD20) ; also on sheet 6
PTB10: U14.58(PTB10/ADC1_SE14/SPI1_PCS0/UART3_RX/FB_AD19/FTM0_FLT1) ; also on sheet 6
PTB11: U14.59(PTB11/ADC1_SE15/SPI1_SCK/UART3_TX/FB_AD18/FTM0_FLT2) ; also on sheet 6
PTB16: R24.2 U14.62(PTB16/SPI1_SOUT/UART0_RX/FTM_CLKIN0/FB_AD17/EWM_IN)
PTB17: R38.2 U14.63(PTB17/SPI1_SIN/UART0_TX/FTM_CLKIN1/FB_AD16/~{EWM_OUT})
PTB18: U14.64(PTB18/CAN0_TX/FTM2_CH0/I2S0_TX_BCLK/FB_AD15/FTM2_QD_PHA) ; also on sheet 6
PTB19: U14.65(PTB19/CAN0_RX/FTM2_CH1/I2S0_TX_FS/~{FB_OE}/FTM2_QD_PHB) ; also on sheet 6
PTB20: U14.66(PTB20/SPI2_PCS0/FB_AD31/CMP0_OUT) ; also on sheet 6
PTB21: R71.2 U14.67(PTB21/SPI2_SCK/FB_AD30/CMP1_OUT)
PTB22: R68.1 U14.68(PTB22/SPI2_SOUT/FB_AD29/CMP2_OUT)
PTB23: U14.69(PTB23/SPI2_SIN/SPI0_PCS5/FB_AD28) ; also on sheet 6
PTC0: U14.70(PTC0/ADC0_SE14/SPI0_PCS4/PDB0_EXTRG/USB_SOF_OUT/FB_AD14/I2S0_TXD1) ; also on sheet 6
PTC1: U14.71(PTC1/LLWU_P6/ADC0_SE15/SPI0_PCS3/~{UART1_RTS}/FTM0_CH0/FB_AD13/I2S0_TXD0) ; also on sheet 6
PTC2: U14.72(PTC2/ADC0_SE4B/CMP1_IN0/SPI0_PCS2/~{UART1_CTS}/FTM0_CH1/FB_AD12/I2S0_TX_FS) ; also on sheet 6
PTC3: U14.73(PTC3/LLWU_P7/CMP1_IN1/SPI0_PCS1/UART1_RX/FTM0_CH2/CLKOUT/I2S0_TX_BCLK) ; also on sheet 6
PTC4: U14.76(PTC4/LLWU_P8/SPI0_PCS0/UART1_TX/FTM0_CH3/FB_AD11/CMP1_OUT) ; also on sheet 6
PTC5: U14.77(PTC5/LLWU_P9/SPI0_SCK/LPTMR0_ALT2/I2S0_RXD0/FB_AD10/CMP0_OUT/FTM0_CH2) ; also on sheet 6
PTC6: U14.78(PTC6/LLWU_P10/CMP0_IN0/SPI0_SOUT/PDB0_EXTRG/I2S0_RX_BCLK/FB_AD9/I2S0_MCLK) ; also on sheet 6
PTC7: U14.79(PTC7/CMP0_IN1/SPI0_SIN/USB_SOF_OUT/I2S0_RX_FS/FB_AD8) ; also on sheet 6
PTC8: U14.80(PTC8/ADC1_SE4B/CMP0_IN2/FTM3_CH4/I2S0_MCLK/FB_AD7) ; also on sheet 6
PTC9: U14.81(PTC9/ADC1_SE5B/CMP0_IN3/FTM3_CH5/I2S0_RX_BCLK/FB_AD6/FTM2_FLT0) ; also on sheet 6
PTC10: U14.82(PTC10/ADC1_SE6B/I2C1_SCL/FTM3_CH6/I2S0_RX_FS/FB_AD5) ; also on sheet 6
PTC11: U14.83(PTC11/LLWU_P11/ADC1_SE7B/I2C1_SDA/FTM3_CH7/I2S0_RXD1/~{FB_RW}) ; also on sheet 6
PTC12: J6.3(A2) U14.84(PTC12/~{UART4_RTS}/FB_AD27/FTM3_FLT0)
PTC13: U14.85(PTC13/~{UART4_CTS}/FB_AD26) ; also on sheet 6
PTC14: J199.3 U14.86(PTC14/UART4_RX/FB_AD25)
PTC15: J199.4 U14.87(PTC15/UART4_TX/FB_AD24)
PTC16: U14.90(PTC16/UART3_RX/ENET0_1588_TMR0/~{FB_CS5}/FB_TSIZ1/~{FB_BE23_16_BLS15_8}) ; also on sheet 6
PTC17: U14.91(PTC17/UART3_TX/ENET0_1588_TMR1/~{FB_CS4}/FB_TSIZ0/~{FB_BE31_24_BLS7_0}) ; also on sheet 6
PTC18: J6.8(B4) U14.92(PTC18/~{UART3_RTS}/ENET0_1588_TMR2/~{FB_TBST}/~{FB_CS2}/~{FB_BE15_8_BLS23_16})
PTD0: U14.93(PTD0/LLWU_P12/SPI0_PCS0/~{UART2_RTS}/FTM3_CH0/FB_ALE/~{FB_CS1}/~{FB_TS}) ; also on sheet 6
PTD1: U14.94(PTD1/ADC0_SE5B/SPI0_SCK/~{UART2_CTS}/FTM3_CH1/~{FB_CS0}) ; also on sheet 6
PTD2: U14.95(PTD2/LLWU_P13/SPI0_SOUT/UART2_RX/FTM3_CH2/FB_AD4/I2C0_SCL) ; also on sheet 6
PTD3: U14.96(PTD3/SPI0_SIN/UART2_TX/FTM3_CH3/FB_AD3/I2C0_SDA) ; also on sheet 6
PTD4: J6.4(B2) U14.97(PTD4/LLWU_P14/SPI0_PCS1/~{UART0_RTS}/FTM0_CH4/FB_AD2/EWM_IN/SPI1_PCS0)
PTD5: J6.5(A3) U14.98(PTD5/ADC0_SE6B/SPI0_PCS2/~{UART0_CTS}/~{UART0_COL}/FTM0_CH5/FB_AD1/~{EWM_OUT}/SPI1_SCK)
PTD6: J6.6(B3) U14.99(PTD6/LLWU_P15/ADC0_SE7B/SPI0_PCS3/UART0_RX/FTM0_CH6/FB_AD0/FTM0_FLT0/SPI1_SOUT)
PTD7: J6.7(A4) U14.100(PTD7/CMT_IRO/UART0_TX/FTM0_CH7/FTM0_FLT1/SPI1_SIN)
PTE0: J15.P8(DAT1) U14.1(PTE0/CLKOUT32K/ADC1_SE4A/SPI1_PCS1/UART1_TX/SDHC0_D1/TRACE_CLKOUT/I2C1_SDA/RTC_CLKOUT)
PTE1: J15.P7(DAT0) U14.2(PTE1/LLWU_P0/ADC1_SE5A/SPI1_SOUT/UART1_RX/SDHC0_D0/TRACE_D3/I2C1_SCL/SPI1_SIN)
PTE2: J15.P5(CLK) U14.3(PTE2/LLWU_P1/ADC0_DP2/ADC1_SE6A/SPI1_SCK/~{UART1_CTS}/SDHC0_DCLK/TRACE_D2)
PTE3: J15.P3(CMD) U14.4(PTE3/ADC0_DM2/ADC1_SE7A/SPI1_SIN/~{UART1_RTS}/SDHC0_CMD/TRACE_D1/SPI1_SOUT)
PTE4: J15.P2(CD/DAT3) U14.5(PTE4/LLWU_P2/SPI1_PCS0/UART3_TX/SDHC0_D3/TRACE_D0)
PTE5: J15.P1(DAT2) U14.6(PTE5/SPI1_PCS2/UART3_RX/SDHC0_D2/FTM3_CH0)
PTE6: J15.G1(SWITCH) U14.7(PTE6/SPI1_PCS3/~{UART3_CTS}/I2S0_MCLK/FTM3_CH1/USB_SOF_OUT)
PTE24: U14.31(PTE24/ADC0_SE17/UART4_TX/I2C0_SCL/~{EWM_OUT}) ; also on sheet 6
PTE25: U14.32(PTE25/ADC0_SE18/UART4_RX/I2C0_SDA/EWM_IN) ; also on sheet 6
PTE26: R73.2 U14.33(PTE26/CLKOUT32K/ENET_1588_CLKIN/~{UART4_CTS}/RTC_CLKOUT/USB_CLKIN) ; also on sheet 6
REXT: C38.1 R58.1 U13.9(REXT)
RMII0_INT_B: J14.2 U13.18(INTRP)
RMII_RXCLK: R57.1 U14.50(PTA18/EXTAL0/FTM0_FLT2/FTM_CLKIN0)
RMII_XTALI: C35.1 U13.8(XI) Y2.1
RMII_XTALO: C29.1 U13.7(XO) Y2.3
RST_TGTMCU_B: D1.C(CATHODE) J9.10(B5) J25.3 R10.2 R11.2 R45.1 U3.7(B1) U14.52(~{RESET}) ; also on sheet 6
RXCLK: R57.2 U13.16(REF_CLK)
RXD0: RN1.4(PIN4) U13.13(RXD0)
RXD1: RN1.3(PIN3) U13.12(RXD1)
SDA_EXTAL: C9.1 U5.17(EXTAL0/PTA18/FTM0_FLT2/FTM_CLKIN0) Y1.3
SDA_JTAG_TCLK: J10.4(B2) U5.12(JTAG_TCLK/SWD_CLK/EZP_CLK/TSI0_CH1/PTA0/~{UART0_CTS}/~{UART0_COL}/FTM0_CH5)
SDA_JTAG_TDI: J10.8(B4) U5.13(JTAG_TDI/EZP_DI/TSI0_CH2/PTA1/UART0_RX/FTM0_CH6)
SDA_JTAG_TDO: J10.6(B3) U5.14(JTAG_TDO/TRACE_SWO/EZP_DO/TSI0_CH3/PTA2/UART0_TX/FTM0_CH7)
SDA_JTAG_TMS: J10.2(B1) R21.2 U5.15(JTAG_TMS/SWD_DIO/TSI0_CH4/PTA3/~{UART0_RTS}/FTM0_CH0)
SDA_LED: D2.C(CATHODE) U5.29(PTD4/SPI0_PCS1/~{UART0_RTS}/FTM0_CH4/EWM_IN/LLWU_P14)
SDA_LED_R: D2.A(ANODE) R17.2
SDA_RST: J10.10(B5) R5.2 R6.1 TP5.1(Pin1) U5.19(~{RESET})
SDA_RST_LED: D1.A(ANODE) R2.2
SDA_RST_TGTMCU_B: J5.2 U5.21(ADC0_SE9/TSI0_CH6/PTB1/I2C0_SDA/FTM1_CH1/FTM1_QD_PHB)
SDA_RST_TGTMCU_J_B: J5.1 J25.1 R10.1 R14.2 U3.2(A1)
SDA_RX_EN: R16.1 R23.2 U7.5(DIR)
SDA_SPI0_CS: R3.2 TP1.1(Pin1) U5.23(ADC0_SE4B/CMP1_IN0/TSI0_CH15/PTC2/SPI0_PCS2/~{UART1_CTS}/FTM0_CH1/I2S0_TX_FS)
SDA_SPI0_RST_B: R18.2 TP6.1(Pin1) U5.22(ADC0_SE15/TSI0_CH14/PTC1/SPI0_PCS3/~{UART1_RTS}/FTM0_CH0/I2S0_TXD0/LLWU_P6)
SDA_SPI0_SCK: U2.3(A) U5.26(PTC5/SPI0_SCK/LPTMR0_ALT2/I2S0_RXD0/CMP0_OUT/LLWU_P9)
SDA_SPI0_SIN: U5.28(CMP0_IN1/PTC7/SPI0_SIN/USB_SOF_OUT/I2S0_RX_FS) U10.5(2A)
SDA_SPI0_SOUT: U5.27(CMP0_IN0/PTC6/SPI0_SOUT/PDB0_EXTRG/I2S0_RX_BCLK/I2S0_MCLK/LLWU_P10) U12.3(A)
SDA_SWD_EN: R18.1 R19.1 U9.6(~{Y2})
SDA_SWD_EN_B: R25.2 U5.16(~{NMI}/~{EZP_CS}/TSI0_CH5/PTA4/FTM0_CH1/LLWU_P3)
SDA_SWD_EN_B_R: R25.1 R26.2 U9.1(A1)
SDA_SWD_EN_R: R12.2 R13.1 R19.2 U2.5(DIR)
SDA_SWD_OE: R3.1 R33.1 U9.4(~{Y1})
SDA_SWD_OE_B: R28.2 U5.20(ADC0_SE8/TSI0_CH0/PTB0/I2C0_SCL/FTM1_CH0/FTM1_QD_PHA/LLWU_P5)
SDA_SWD_OE_B_R: R27.1 R28.1 U9.3(A2)
SDA_SWD_OE_R: R33.2 R37.2 R39.1 U12.5(DIR)
SDA_USB_CONN_DN: J26.2(P2) R22.1 U4.1(A1)
SDA_USB_CONN_DP: J26.3(P3) R20.1 U6.1(A1)
SDA_USB_DN: R22.2 U5.4(USB0_DM)
SDA_USB_DP: R20.2 U5.3(USB0_DP)
SDA_USB_P5V_SENSE: R7.1 R8.2 U5.30(ADC0_SE6B/PTD5/SPI0_PCS2/~{UART0_CTS}/~{UART0_COL}/FTM0_CH5/~{EWM_OUT})
SDA_USBSHIELD: J26.S1(SHLD1) J26.S2(SHLD2) J26.S3(SHLD3) J26.S4(SHLD4) L2.1
SDA_VOUT33: C11.1 J7.2 U5.5(VOUT33)
SDA_XTAL: C6.1 U5.18(XTAL0/PTA19/FTM1_FLT0/FTM_CLKIN1/LPTMR0_ALT1) Y1.1
SHIELD_K64USB: J22.S1(SHLD1) J22.S2(SHLD2) J22.S3(SHLD3) J22.S4(SHLD4) L4.1
SW1_RST_B: C2.1 J25.2 SW1.2(SW2)
SWD_CLK_TGTMCU: J8.2 J9.4(B2) J11.2
SWD_CLK_TGTMCU_BUF: J8.1 U2.4(B)
SWD_DIO_TGTMCU_BUF: J12.1 U10.2(2B) U12.4(B)
TC_EXTAL_TP: TP9.1(Pin1) U5.10(EXTAL32)
TC_SDA_USB_ID_TP: J26.4(P4) TP7.1(Pin1)
TC_USB_ID_TP: J22.4(P4) R72.1 TP15.1(Pin1)
TC_XTAL_TP: TP10.1(Pin1) U5.9(XTAL32)
TP_2102_A: TP3.1(Pin1) U3.3(A2)
TP_2102_B: TP2.1(Pin1) U3.6(B2)
TRACE_SWO: J9.6(B3) R80.1
UART1_RX_TGTMCU_BUF: R24.1 U7.4(B)
UART1_RX_TGTMCU_R: U5.25(PTC4/SPI0_PCS0/UART1_TX/FTM0_CH3/CMP1_OUT/LLWU_P8) U7.3(A)
UART1_TX_TGTMCU_BUF: R38.1 U10.1(1B)
UART1_TX_TGTMCU_R: U5.24(CMP1_IN1/PTC3/SPI0_PCS1/UART1_RX/FTM0_CH2/I2S0_TX_BCLK/LLWU_P7) U10.6(1A)
USB_CONN_DN: J22.2(P2) R49.1 U16.1(A1)
USB_CONN_DP: J22.3(P3) R46.1 U18.1(A1)
V_TGTMCU: C7.1 C23.1 R2.1 R11.1 SH1.1 U2.6(VCCB) U3.8(VCCB) U7.6(VCCB) U10.8(VCCB) U12.6(VCCB)
VOUT33_K64: C59.1 TP12.1(Pin1) U14.12(VOUT33)
VREFH: D4.C(CATHODE) R52.2 R53.1 R54.2 U14.23(VREFH)
VREGIN_K64: C33.1 J16.1 U14.13(VREGIN)
VTRG_EN: R29.2 R30.1 R34.2 U11.3(ENABLE)
VTRG_FAULT_B: R35.2 U5.32(PTD7/CMT_IRO/UART0_TX/FTM0_CH7/FTM0_FLT1) U11.4(~{FAULT})
XTAL32_RTC: R62.1 U14.28(XTAL32)
XTAL_32.768KHz: C44.1 R62.2 R65.2 Y3.1
XTAL_K64_MAIN: R74.1 U14.51(PTA19/XTAL0/FTM1_FLT0/FTM_CLKIN1/LPTMR0_ALT1)
N20614543: C34.1 D3.3(COM_ANODE) R50.2 U13.24(~{RST})
N20654921: RN1.2(PIN2) U13.17(RXER)
N20657567: J13.14(L4) R36.2

Not connected (* = marked no-connect by the designer): J9 7(A4)* 8(B4)* 9(A5)*; J10 7(A4)* 9(A5)*

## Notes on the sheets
sheet 1
- Table of Contents
- Revisions & Change Log
- 1
- Title
- 2
- Block Diagram
- Rev
- Description
- Date
- Approved
- 3
- KL26Z MCU
- X1
- Initial Draft
- Oct 18
- Chung
- 4
- OpenSDA INTERFACE
- 5
- I/O Headers and Power Supply
- X2
- Feedbacks Implemented
- Oct 22
- Chung
- X3
- Feedbacks from Chung Implemented
- Oct 23
- Chung
- Components changed as per the
  feedbacks
- X4
- Oct 24
- Chung
- RF and Bluetooth headers added
- X5
- Oct 28
- Chung
- X6
- Arduino connections added
- Nov 1
- Chung
- X7
- Net review and fix
- Nov 3
- Chung
- Release to production,
  prototype build
- A
- Nov 8
- Chung
- openSDA reset capacitor fix
- A1
- Nov 22
- del Rey
- Release to production,
  production build
- B
- Jan 20
- Chung
- C
- Release to production,
  production build
- Feb 06
- Chung
- Fixing I2C swap to headers
- D
- Feb 26
- Chung
- D1
- Enhancing USB PWR input filter
  for robustness
- Mar 18
- Chung
- F
- Swapping J2.2 connection to PTB20
- Mar 20
- Chung
- FREEDOM K64F
sheet 2
- OPTIONAL USB HOST FUNCTIONALITY
- Layout Note:Connect C513
  directly between VDDA and
  VSSA pins
- POPULATE THESE
  PARTS FOR
  USB HOST FUNCTIONALITY
  ELECTRICAL PROTECTION
  IS NOT PROVIDED.
  USE IT AT YOUR OWN RISK
- R
- G
- B
- LED FEATURE
- SWD CONNECTOR
- SHORTING HEADER ON BOTTOM LAYER
  Jumper is shorted by a cut-trace
  on bottom layer. Cutting the trace
  will effectively isolate the on-board
  MCU from the OpenSDA
  debug interface.
sheet 3
- OpenSDA Interface
- RESET
- 1-2: Default.
  2-3: Reset signal direct to the MCU,
  to use when OpenSDA is not powered.
- RST Push Button
  Bypass
- TARGET MCU
  INTERFACE
  SIGNALS
- Output to system
  from Level shifter
- UART1_RX_TGTMCU
- Output to system
  from Level shifter
- Isolation
  Resistors
- UART1_TX_TGTMCU
- PU/PD LOGIC:
  SERIAL INTERFACE
  IS ALWAYS RESET
  WHEN USB PORT
  IS DISCONNECTED
- Output to system
  from Level shifter
- SWD_DIO_TGTMCU
- OPEN SDA
  POWER OUTPUTS
- HW Designer: Rafael del Rey
- OPEN SDA
  INPUT POWER
- i
- path
- i
- path
- Note: You can power openSDA
  with your own power supplies
  by replacing this rail
  (SDA_VOUT33)
  with your 3.3V power supply rail
- 3.3VDC, 10mA should be provided
  to this rail (P3V3_SDA)
  in order to power openSDA
  module
- SHORTING HEADER ON BOTTOM LAYER
  Jumper is shorted by a cut-trace
  on bottom layer. Cutting the trace
  will effectively isolate the on-board
  MCU from the OpenSDA
  debug interface.
- OpenSDA INTERFACE JTAG CONNECTOR
- PWR SWITCH
- (To enable 5v from
  USB connector)
- Isolation and level shift stage
  (for 1.8 to 5V compatibility)
- PU/PD LOGIC (DIR PIN):
  BUFFER IS TRISTATED WHEN
  P3V3_SDA IS UNPOWERED
- i
- path
- SDA_VOUT33 can provide up to 120mA
  of power at 3.3VDC to your system
  P5V_TRG_SDA can provide up to 450mA
  (per USB spec) of power at 5VDC
  to your system
- ACTIVE HIGH
- I/O POWER
  INPUT
- i
- path
- V_BRD is supported
  from 1.8V to 5V
- Power should be provided
  to this rail for the logic
  related to your platform I/O
- {For enablement purposes only}
sheet 4
- SD_CARD SECTION
- SD Card
- SD_CARD_DETECT
- Detect pin is a normally open switch
  that shorts with VDD when card is inserted.
  (positive logic)
- RF/WIFI
- Bluetooth
- SCK
- CE
- MOSI
- CS
- MISO
- IRQ
- BT_TX
- BT_RX
- Add-on WIFI module: RF24L01+ - Nordic 2.4G Radio
- Add-on BT module: JY-MCU BT BOARD V1.05 BT
sheet 5
- LAYOUT NOTES:
  1. The TRD+/TRD- pairs should be routed with a 100ohm
  differential impedance and a 50ohm single ended
  (characteristic) impedance.
  2. The trace lengths within a TRD+/TRD- differential pair
  should be matched.
  3. The distance between each TRD+/TRD- differential
  pair should be 50mils or more.
- RMII0_MDIO
- RMII0_MDC
- RMII0_RXD_0
- RMII0_RXD_1
- RMII0_MDC
- RMII0_CRS_DV
- RMII0_MDIO
- RMII0_TXD_0
- RMII0_TXD_1
- RMII0_TXEN
- RMII0_RXD_0
- RMII0_RXD_1
- RMII0_TXD_0
- RMII0_RXER
- RMII0_TXD_1
- RMII0_TXEN
- RMII0_CRS_DV
- RMII0_RXER
- PHY_INT_1
- PHY_RESET_B must be a GPIO
  toggeld after CLKIN is active.
